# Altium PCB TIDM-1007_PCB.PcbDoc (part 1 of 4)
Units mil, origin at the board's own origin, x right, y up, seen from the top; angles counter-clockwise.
Board outline 9645.67 x 3346.46 mil, 6 copper layers (Top Layer, Signal Layer 1, Signal Layer 2, Signal Layer 3, Signal Layer 4, Bottom Layer), stack 60.2 mil thick; 189 components, 109 nets, 620 pads, 278 vias.
Unrouted connection lines stored in the file: 5.
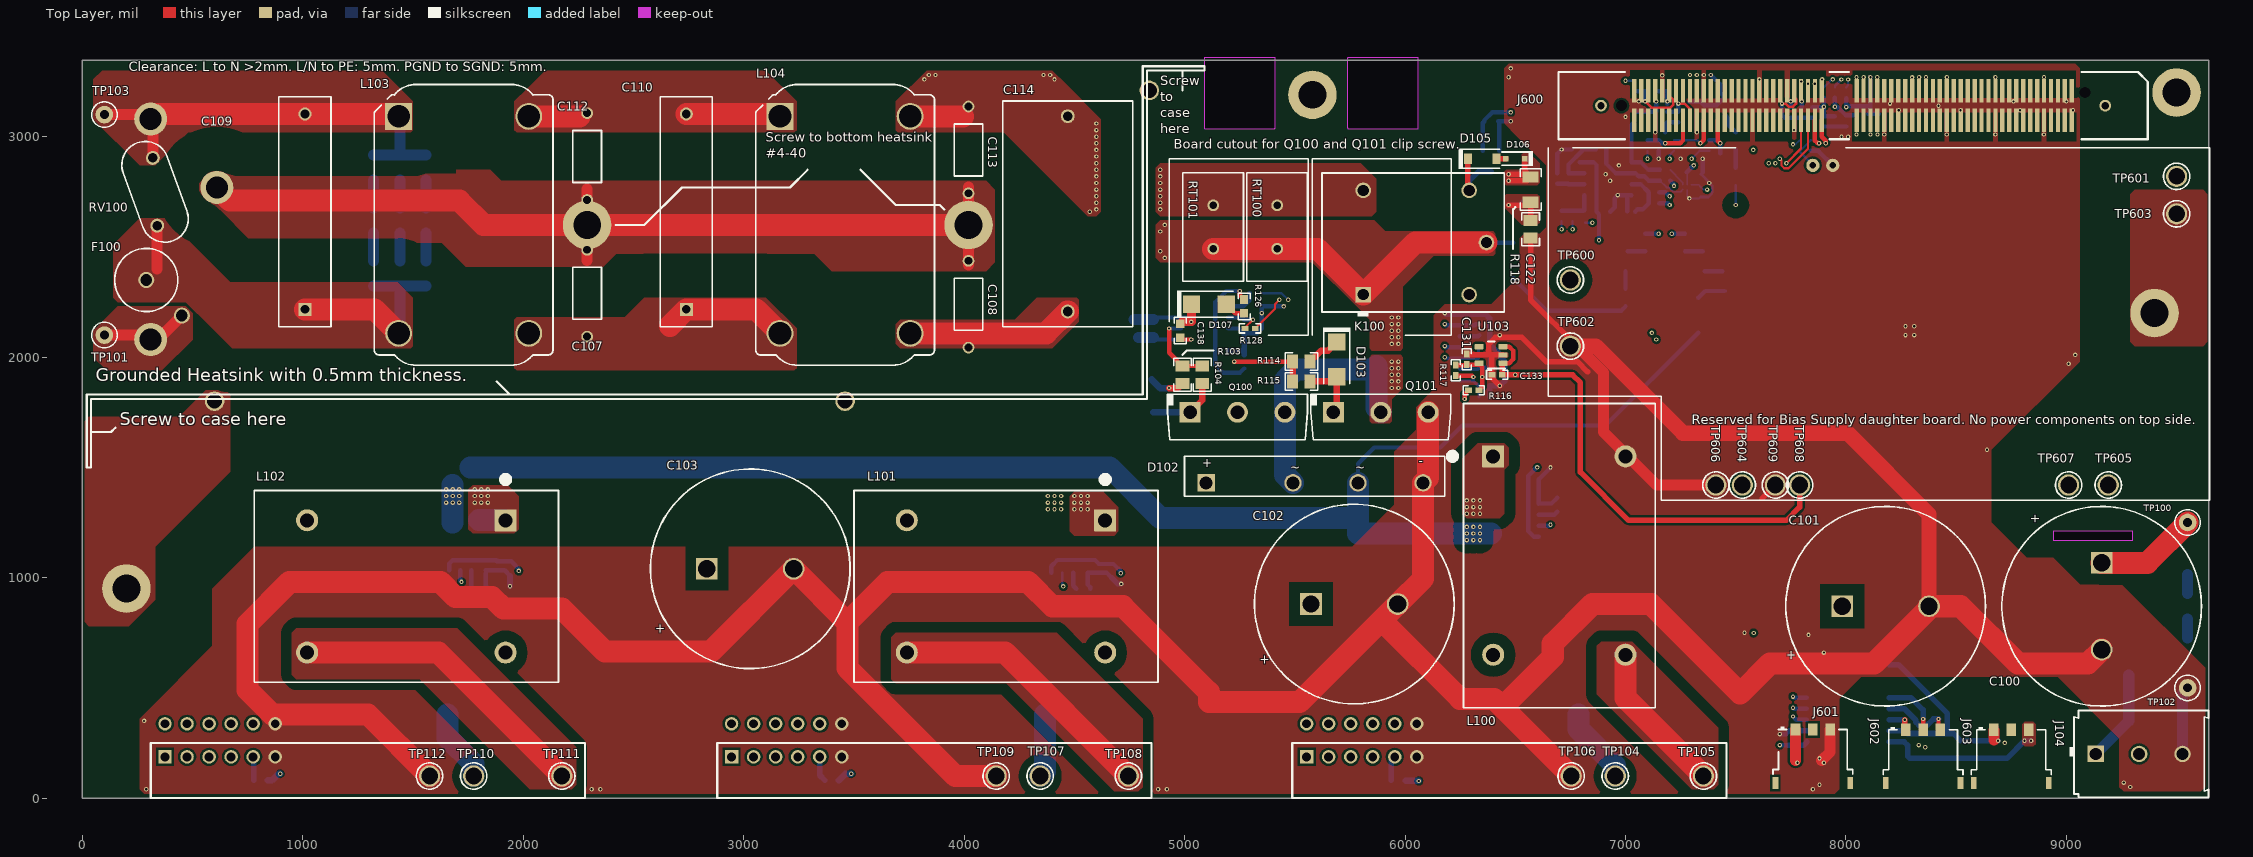
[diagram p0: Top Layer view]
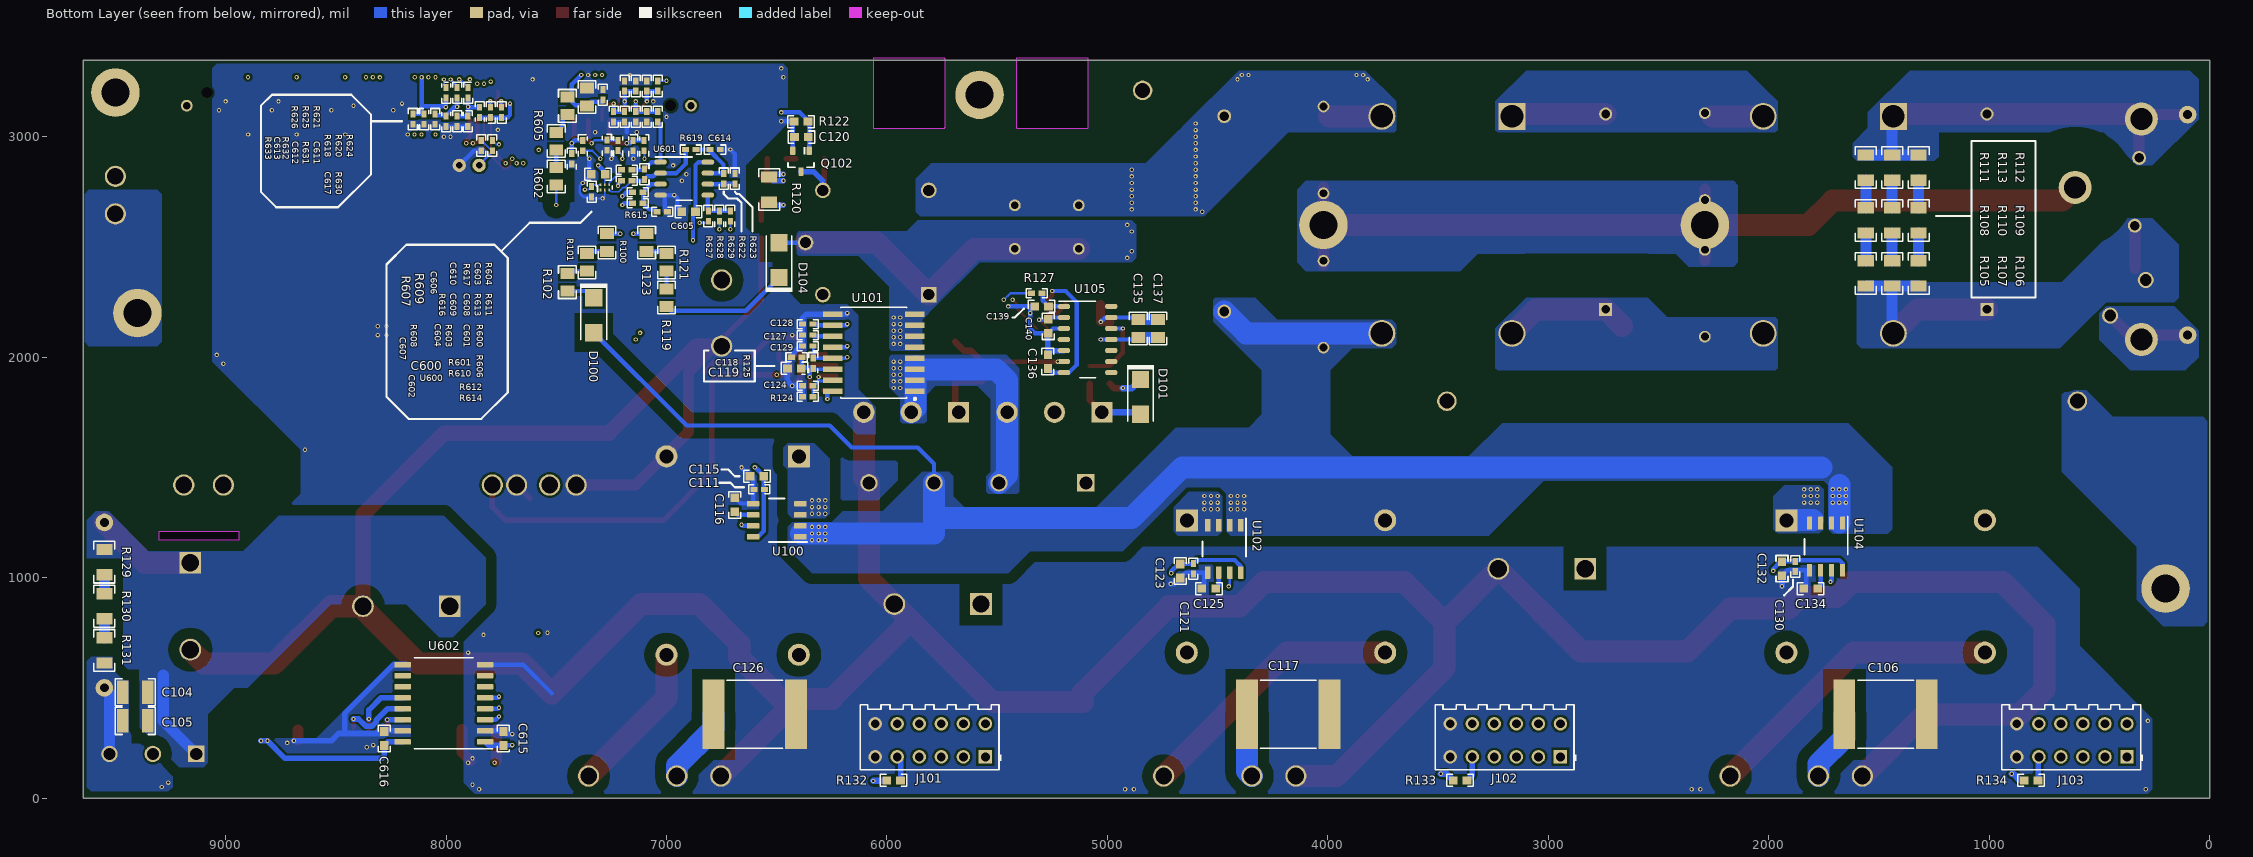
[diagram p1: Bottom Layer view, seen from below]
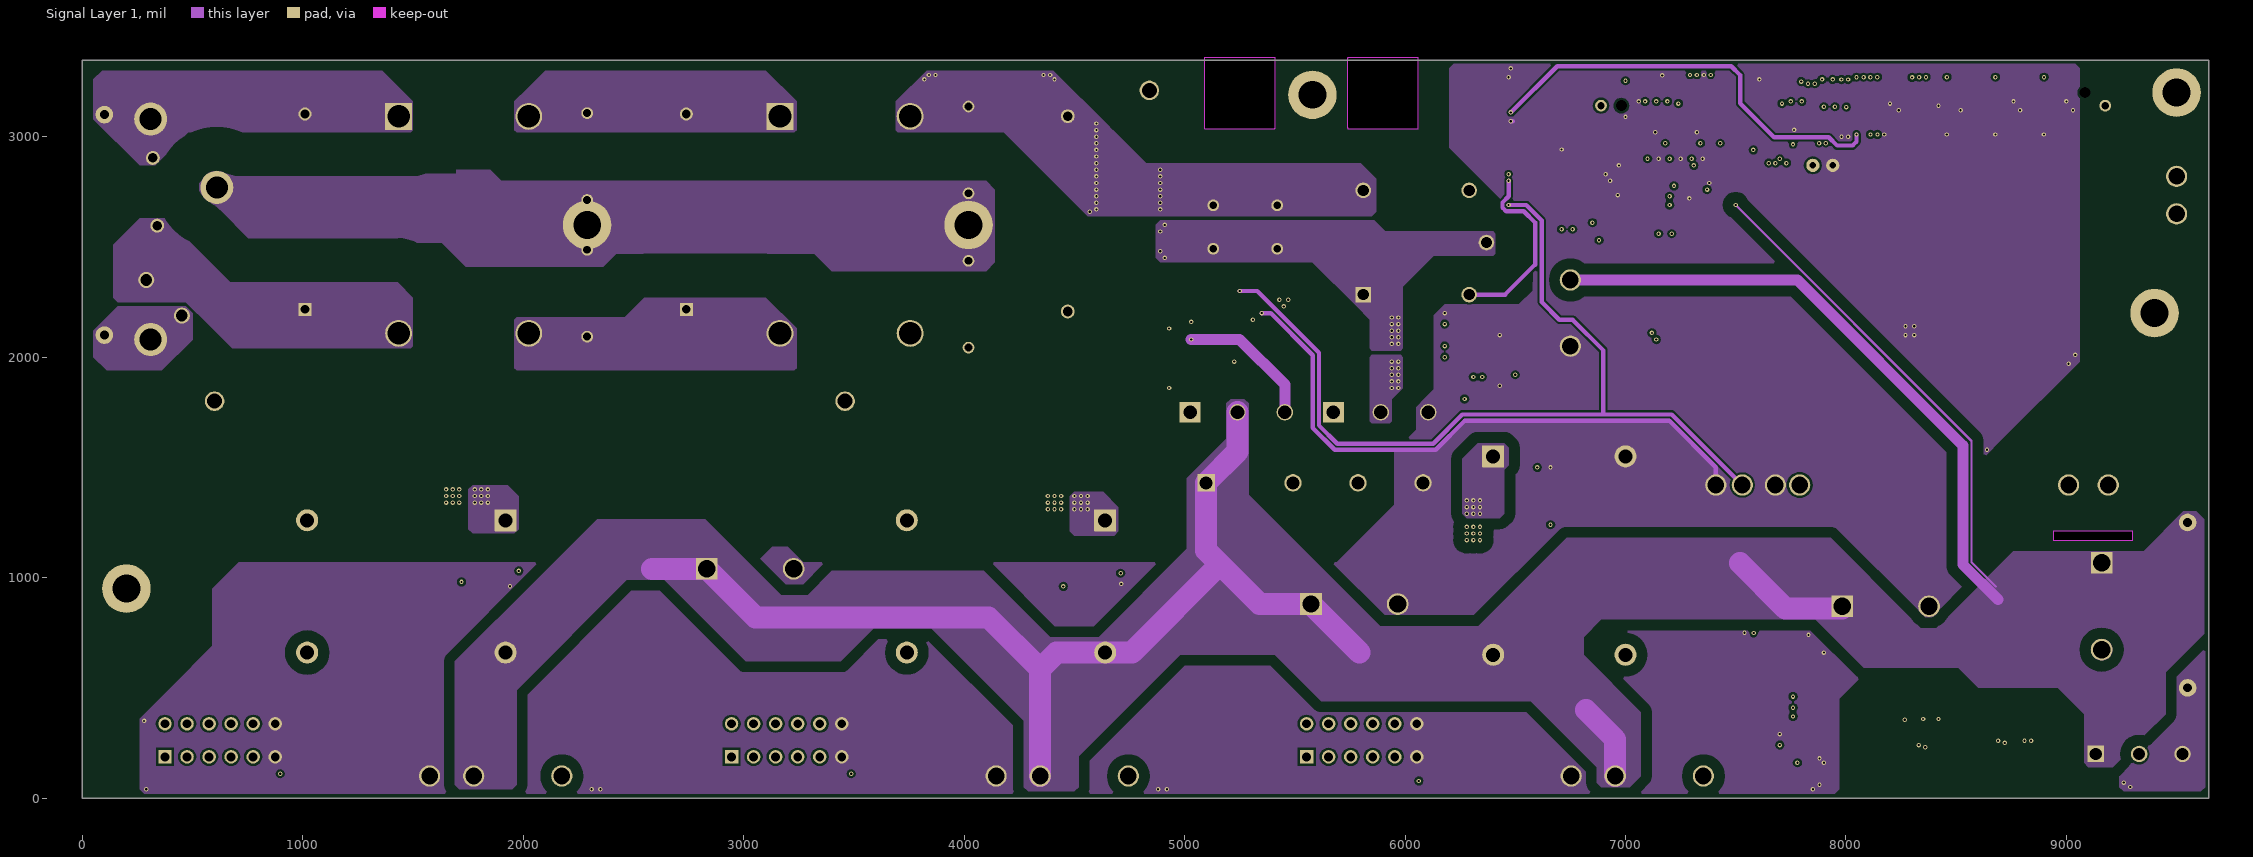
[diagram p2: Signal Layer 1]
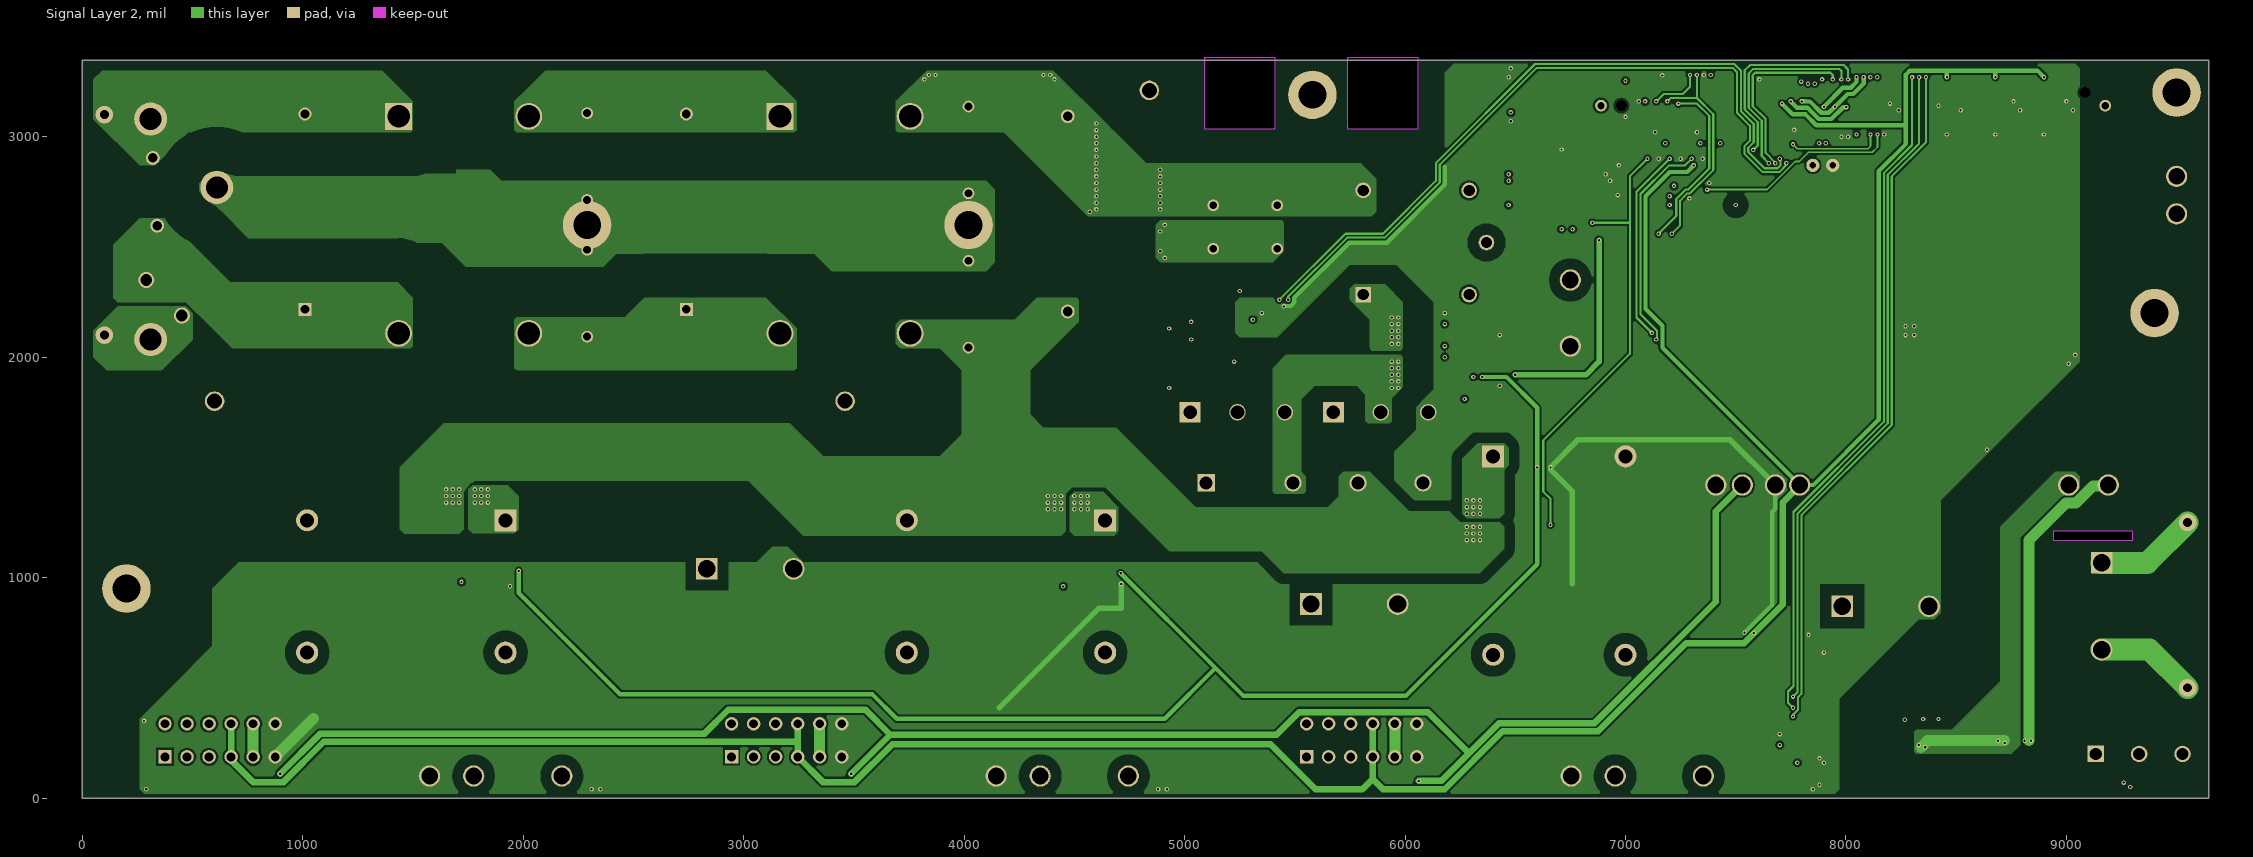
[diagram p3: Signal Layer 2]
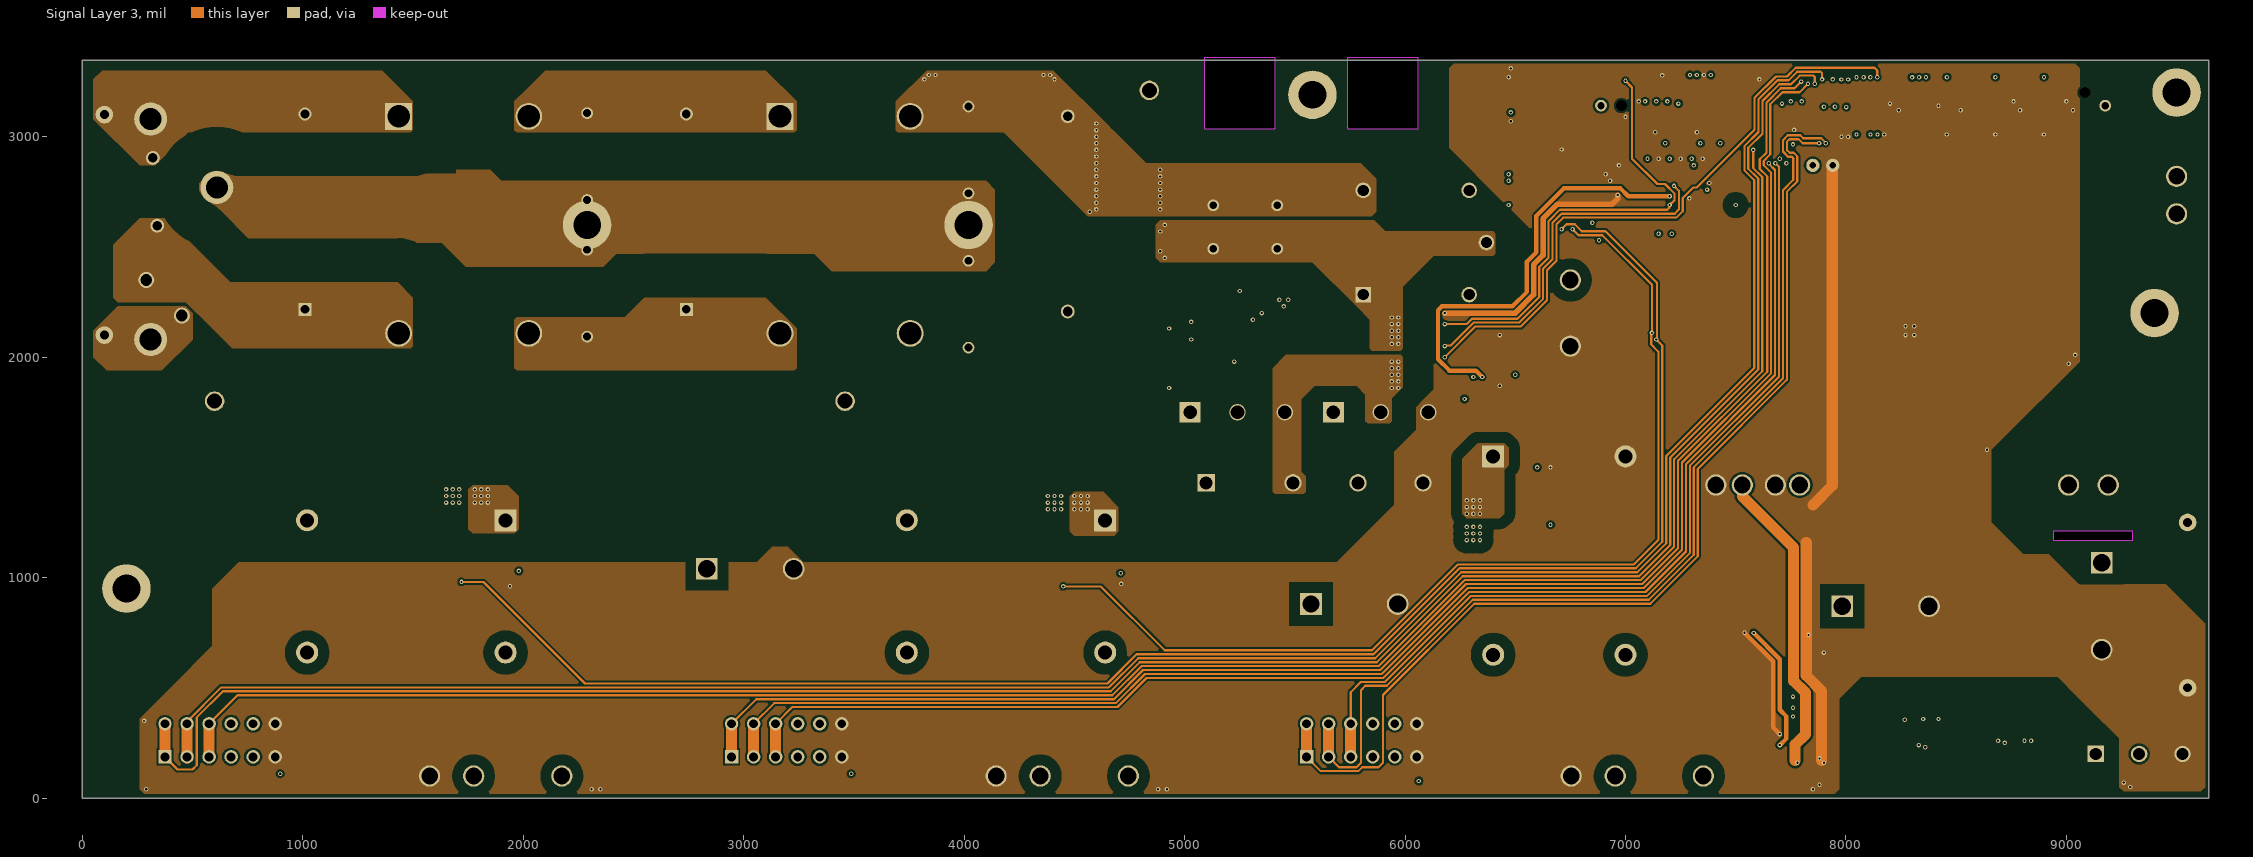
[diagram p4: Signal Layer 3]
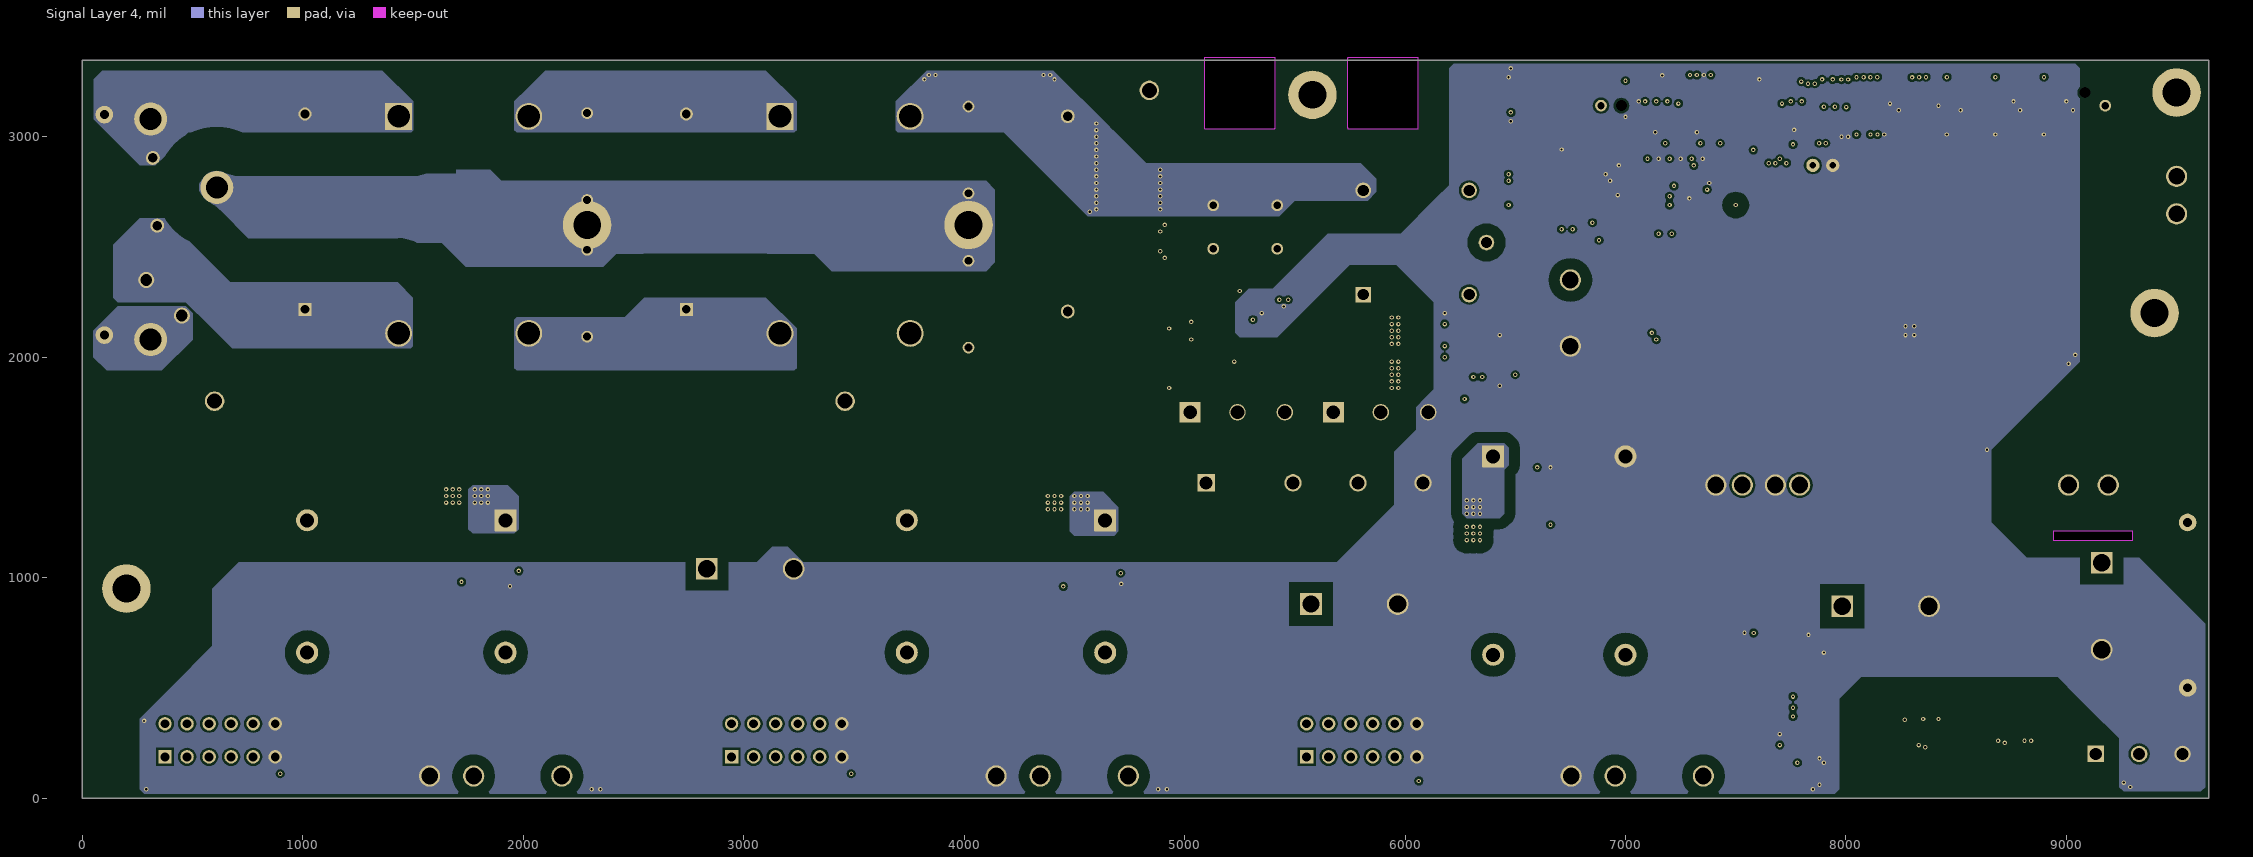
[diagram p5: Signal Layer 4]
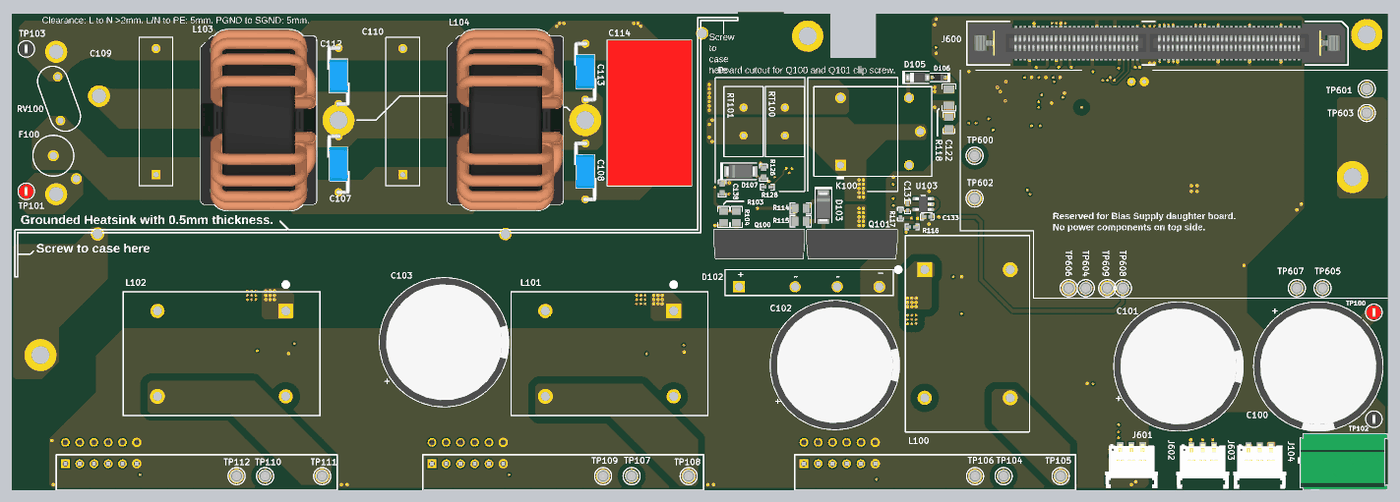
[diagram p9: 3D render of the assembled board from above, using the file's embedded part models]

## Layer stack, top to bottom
Top Solder: solder mask 0.4, Solder Resist, Dk 3.5
Top Layer: signal copper 2.8
Dielectric1: prepreg 7, Dk 4.2
Signal Layer 1: signal copper 1.4
Dielectric 3: core 14, FR-4, Dk 4.2
Signal Layer 2: signal copper 1.4
Dielectric 4: prepreg 7, Dk 4.2
Signal Layer 3: signal copper 1.4
Dielectric 5: core 14, FR-4, Dk 4.2
Signal Layer 4: signal copper 1.4
Dielectric 2: prepreg 7, Dk 4.2
Bottom Layer: signal copper 2.8
Bottom Solder: solder mask 0.4, Solder Resist, Dk 3.5

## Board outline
0,0 9645.67,0 9645.67,3346.46 0,3346.46
cut-out: 8940,1170 9300,1170 9300,1210 8940,1210
cut-out: 5089,3040 ccw(c5092.52,3040) 5092.52,3036.48 5407.48,3036.48 ccw(c5407.48,3040) 5411,3040 5411,3354.96 ccw(c5407.48,3354.96) 5407.48,3358.48 5092.52,3358.48 ccw(c5092.52,3354.96) 5089,3354.96
cut-out: 5739,3040 ccw(c5742.52,3040) 5742.52,3036.48 6057.48,3036.48 ccw(c6057.48,3040) 6061,3040 6061,3354.96 ccw(c6057.48,3354.96) 6057.48,3358.48 5742.52,3358.48 ccw(c5742.52,3354.96) 5739,3354.96

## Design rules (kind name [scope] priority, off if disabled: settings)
AcuteAngle [All] p1: minimum=4.50000000000000E+0001 checktracksonly=FALSE
AssemblyTestPointUsage [All] p1: valid=2
Clearance Clearance_3 [InNet('EARTH') vs Not InNet('EARTH') And Not InNet('12VS')] p1: gap=200 ignorepadtopadclearanceinfootprint=FALSE except(0: Arc-Hole Track-Hole SMDPad-Hole THPad-Hole Via-Hole Fill-Hole Poly-Hole Region-Hole Text-Hole)
Clearance Clearance_1 [InNetClass('HV') vs InNetClass('MV')] p2: gap=25 ignorepadtopadclearanceinfootprint=FALSE except(0: Arc-Hole Track-Hole SMDPad-Hole THPad-Hole Via-Hole Fill-Hole Poly-Hole Region-Hole Text-Hole)
Clearance Clearance_2 [InNetClass('HV') vs Not InNetClass('HV')] p3: gap=50 ignorepadtopadclearanceinfootprint=FALSE except(0: Arc-Hole Track-Hole SMDPad-Hole THPad-Hole Via-Hole Fill-Hole Poly-Hole Region-Hole Text-Hole)
Clearance Clearance_Keepouts [((IsTrack Or IsArc) And Not InPoly) And IsFree and IsKeepOut vs ((IsTrack Or IsArc) And Not InPoly) And IsFree and IsKeepOut] p4: gap=0 ignorepadtopadclearanceinfootprint=FALSE
Clearance Clearance_BoardEdge_MountingHoles [OnCopper and InComponentClass('Mounting Holes') vs IsKeepOut] p5: gap=40 ignorepadtopadclearanceinfootprint=FALSE except(0: Arc-Hole Track-Hole SMDPad-Hole THPad-Hole Via-Hole Fill-Hole Poly-Hole Region-Hole Text-Hole)
Clearance Clearance_BoardEdge_Poly [OnCopper and InPoly vs IsKeepOut] p6: gap=25 ignorepadtopadclearanceinfootprint=FALSE except(0: Arc-Hole Track-Hole SMDPad-Hole THPad-Hole Via-Hole Fill-Hole Poly-Hole Region-Hole Text-Hole)
Clearance Clearance_BoardEdge [OnCopper and Not InComponentClass('Logo') and not InComponentClass('FiducialMark') and not InRegion(1000,500,4000,800) and Not IsKeepout vs IsKeepOut] p7: gap=75 ignorepadtopadclearanceinfootprint=FALSE except(0: Arc-Hole Track-Hole SMDPad-Hole THPad-Hole Via-Hole Fill-Hole Poly-Hole Region-Hole Text-Hole)
Clearance Clearance_Poly [InPolygon] p8: gap=10 ignorepadtopadclearanceinfootprint=FALSE except(0: Arc-Hole Track-Hole SMDPad-Hole THPad-Hole Via-Hole Fill-Hole Poly-Hole Region-Hole Text-Hole)
Clearance [All] p9: gap=7.87 ignorepadtopadclearanceinfootprint=FALSE except(0: Arc-Hole Track-Hole SMDPad-Hole THPad-Hole Via-Hole Fill-Hole Poly-Hole Region-Hole Text-Hole)
ComponentClearance ComponentClearance_MountingHoles_FiducialMarks [InComponentClass('Mounting Holes') vs InComponentClass('FiducialMark')] p1: gap=20 collisioncheckmode=3 verticalgap=10 showdistances=FALSE
ComponentClearance ComponentClearance_Shunt [InComponentClass('Header') vs InComponentClass('Shunt')] p2: gap=0 collisioncheckmode=3 verticalgap=0 showdistances=FALSE
ComponentClearance ComponentClearance_Logo [InComponentClass('Logo')] p3: gap=5 collisioncheckmode=3 verticalgap=10 showdistances=FALSE
ComponentClearance ComponentClearance_ScrewToNut [(HasFootprint('NY PMS 440 0025 PH')) vs (HasFootprint('Keystone_1902C'))] p4: gap=20 collisioncheckmode=3 verticalgap=100000 showdistances=FALSE
ComponentClearance ComponentClearance_MountingHoles [InComponentClass('Mounting Holes')] p5: gap=20 collisioncheckmode=3 verticalgap=10 showdistances=FALSE
ComponentClearance ComponentClearance_SmallPassives [HasFootprint('0201*') or HasFootprint('0402*') or HasFootprint('0508') or HasFootprint('0603*') or HasFootprint('0612') or HasFootprint('0805*') or HasFootprint('0815*') or HasFootprint('0830*') or HasFootprint('1206*') or HasFootprint('1210*') or HasFootprint('1808*') or HasFootprint('1812*') or HasFootprint('1825*') or HasFootprint('2010*') or HasFootprint('2220*') or HasFootprint('2225*') or HasFootprint('2512*') or HasFootprint('2728*') or HasFootprint('3518*') vs HasFootprint('0201*') or HasFootprint('0402*') or HasFootprint('0508') or HasFootprint('0603*') or HasFootprint('0612') or HasFootprint('0805*') or HasFootprint('0815*') or HasFootprint('0830*') or HasFootprint('1206*') or HasFootprint('1210*') or HasFootprint('1808*') or HasFootprint('1812*') or HasFootprint('1825*') or HasFootprint('2010*') or HasFootprint('2220*') or HasFootprint('2225*') or HasFootprint('2512*') or HasFootprint('2728*') or HasFootprint('3518*')] p6: gap=20 collisioncheckmode=3 verticalgap=20 showdistances=FALSE
ComponentClearance ComponentClearance_THtoSMT [IsThruComponent vs IsSMTComponent] p7: gap=10 collisioncheckmode=3 verticalgap=10 showdistances=FALSE
ComponentClearance ComponentClearance_THtoTH [IsThruComponent vs IsThruComponent] p8: gap=10 collisioncheckmode=3 verticalgap=10 showdistances=FALSE
ComponentClearance [All] p9: gap=10 collisioncheckmode=3 verticalgap=10 showdistances=FALSE
DiffPairsRouting [All] p1: maxlimit=100 minlimit=10 mostfreqgap=10 toplayer_minwidth=15 toplayer_maxwidth=15 toplayer_prefwidth=15 midlayer1_minwidth=15 midlayer1_maxwidth=15 midlayer1_prefwidth=15 midlayer2_minwidth=15 midlayer2_maxwidth=15 midlayer2_prefwidth=15 midlayer3_minwidth=15 midlayer3_maxwidth=15 midlayer3_prefwidth=15 midlayer4_minwidth=15 midlayer4_maxwidth=15 midlayer4_prefwidth=15 bottomlayer_minwidth=15 bottomlayer_maxwidth=15 bottomlayer_prefwidth=15 maxuncoupledlength=1000
FabricationTestPointUsage TestPointUsage [All] p1: valid=2 allowmultiple=FALSE
FabricationTestpoint Testpoint [All] p1: side=3 testpointundercomponent=TRUE minsize=40 maxsize=100 preferedsize=60 minholesize=0 maxholesize=40 preferedholesize=32 testpointgrid=1 allowsidetop=TRUE allowsidebottom=TRUE usegrid=TRUE gridtolerance=0.01
FanoutControl Fanout_LCC [IsLCC] p1: bgadir=Out bgaviamode=Centered fanoutstyle=Auto fanoutdirection=Alternating viagrid=1 // Fanout_LCC (Default Rule)
FanoutControl Fanout_BGA [IsBGA] p2: bgadir=Out bgaviamode=Centered fanoutstyle=Auto fanoutdirection=Alternating viagrid=1 // Fanout_BGA (Default Rule)
FanoutControl Fanout_Default [All] p4: bgadir=Out bgaviamode=Centered fanoutstyle=Auto fanoutdirection=Alternating viagrid=1 // Fanout_Default (Default Rule)
FanoutControl Fanout_Small [(CompPinCount < 5)] p5: bgadir=Out bgaviamode=Centered fanoutstyle=Auto fanoutdirection=OutThenIn viagrid=1 // Fanout_Small (Default Rule)
Height [All] p1: minheight=0 maxheight=3000 prefheight=500
HoleSize [All] p1: absolutevalues=TRUE maxlimit=251 minlimit=7 maxpercent=80.000 minpercent=20.000
MinimumAnnularRing MinimumAnnularRing_ThermalPadVias [IsVia and InAnyComponent] p1: minimumring=5.91
MinimumAnnularRing [All] p2: minimumring=4.9
MinimumSolderMaskSliver MinimumSolderMaskSliver_Logo [InComponentClass('Logo') vs InComponentClass('Logo')] p1: minsoldermaskwidth=0.7
MinimumSolderMaskSliver [All] p2: minsoldermaskwidth=2
PlaneConnect [All] p1: planeconnectstyle=Direct reliefexpansion=10 reliefentries=4 reliefconductorwidth=10 reliefairgap=10
PolygonConnect PolygonConnect_26 [All vs IsNamedPolygon('12VP') Or  IsNamedPolygon('D106_1') Or  IsNamedPolygon('HVBUS') Or  IsNamedPolygon('Earth') Or  IsNamedPolygon('L101_1') Or  IsNamedPolygon('C110_2') Or  IsNamedPolygon('Earth') Or  IsNamedPolygon('SWNODE3') Or  IsNamedPolygon('C107_1') Or  IsNamedPolygon('L102_1') Or  IsNamedPolygon('L100_1') Or  IsNamedPolygon('AC_N') Or  IsNamedPolygon('C109_1') Or  IsNamedPolygon('Earth') Or  IsNamedPolygon('C109_1') Or  IsNamedPolygon('F100_2') Or  IsNamedPolygon('-BRDG_N') Or  IsNamedPolygon('C109_1') Or  IsNamedPolygon('-BRDG_N') Or  IsNamedPolygon('Earth') Or  IsNamedPolygon('C113_2') Or  IsNamedPolygon('Earth') Or  IsNamedPolygon('C110_2') Or  IsNamedPolygon('C107_1') Or  IsNamedPolygon('SWNODE2') Or  IsNamedPolygon('SGND2') Or  IsNamedPolygon('C113_2') Or  IsNamedPolygon('C109_2') Or  IsNamedPolygon('L101_1') Or  IsNamedPolygon('AC_N') Or  IsNamedPolygon('C113_2') Or  IsNamedPolygon('SWNODE2') Or  IsNamedPolygon('-BRDG_N') Or  IsNamedPolygon('C113_2') Or  IsNamedPolygon('AC_N') Or  IsNamedPolygon('5VS') Or  IsNamedPolygon('C110_2') Or  IsNamedPolygon('PGND') Or  IsNamedPolygon('HVBUS') Or  IsNamedPolygon('C107_1') Or  IsNamedPolygon('F100_2') Or  IsNamedPolygon('AC_L') Or  IsNamedPolygon('SGND2') Or  IsNamedPolygon('-BRDG_N') Or  IsNamedPolygon('C109_1') Or  IsNamedPolygon('L101_1') Or  IsNamedPolygon('C109_2') Or  IsNamedPolygon('C110_2') Or  IsNamedPolygon('C109_2') Or  IsNamedPolygon('-BRDG_N') Or  IsNamedPolygon('C110_2') Or  IsNamedPolygon('C109_1') Or  IsNamedPolygon('C109_2') Or  IsNamedPolygon('F100_2') Or  IsNamedPolygon('AC_N') Or  IsNamedPolygon('C109_2') Or  IsNamedPolygon('F100_2') Or  IsNamedPolygon('C107_1') Or  IsNamedPolygon('C113_2') Or  IsNamedPolygon('F100_2') Or  IsNamedPolygon('AC_N') Or  IsNamedPolygon('C110_2') Or  IsNamedPolygon('SWNODE1') Or  IsNamedPolygon('C109_2') Or  IsNamedPolygon('C109_1') Or  IsNamedPolygon('C107_1') Or  IsNamedPolygon('F100_2') Or  IsNamedPolygon('C107_1') Or  IsNamedPolygon('AC_N') Or  IsNamedPolygon('L100_1') Or  IsNamedPolygon('Earth') Or  IsNamedPolygon('C113_2') Or  IsNamedPolygon('SWNODE1') Or  IsNamedPolygon('AC_L') Or  IsNamedPolygon('L102_1') Or  IsNamedPolygon('SWNODE3') Or  IsNamedPolygon('AC_L')] p1: connectstyle=Direct reliefconductorwidth=10 reliefentries=4 polygonreliefangle="90 Angle" airgapwidth=10
PolygonConnect PolygonConnect_25 [All vs IsNamedPolygon('12VP') Or  IsNamedPolygon('SWNODE2') Or  IsNamedPolygon('F100_2') Or  IsNamedPolygon('AC_N') Or  IsNamedPolygon('C113_2') Or  IsNamedPolygon('-BRDG_N') Or  IsNamedPolygon('L102_1') Or  IsNamedPolygon('Earth') Or  IsNamedPolygon('SWNODE3') Or  IsNamedPolygon('L101_1') Or  IsNamedPolygon('C109_2') Or  IsNamedPolygon('C107_1') Or  IsNamedPolygon('C110_2') Or  IsNamedPolygon('C109_2') Or  IsNamedPolygon('C110_2') Or  IsNamedPolygon('5VS') Or  IsNamedPolygon('L101_1') Or  IsNamedPolygon('-BRDG_N') Or  IsNamedPolygon('AC_L') Or  IsNamedPolygon('AC_N') Or  IsNamedPolygon('F100_2') Or  IsNamedPolygon('AC_N') Or  IsNamedPolygon('-BRDG_N') Or  IsNamedPolygon('AC_L') Or  IsNamedPolygon('L102_1') Or  IsNamedPolygon('C109_2') Or  IsNamedPolygon('L100_1') Or  IsNamedPolygon('C113_2') Or  IsNamedPolygon('C113_2') Or  IsNamedPolygon('C113_2') Or  IsNamedPolygon('C109_2') Or  IsNamedPolygon('Earth') Or  IsNamedPolygon('AC_N') Or  IsNamedPolygon('C107_1') Or  IsNamedPolygon('C107_1') Or  IsNamedPolygon('F100_2') Or  IsNamedPolygon('C109_1') Or  IsNamedPolygon('-BRDG_N') Or  IsNamedPolygon('C110_2') Or  IsNamedPolygon('AC_L') Or  IsNamedPolygon('C113_2') Or  IsNamedPolygon('Earth') Or  IsNamedPolygon('C109_1') Or  IsNamedPolygon('C110_2') Or  IsNamedPolygon('SWNODE3') Or  IsNamedPolygon('C109_1') Or  IsNamedPolygon('C109_2') Or  IsNamedPolygon('C107_1') Or  IsNamedPolygon('F100_2') Or  IsNamedPolygon('D106_1') Or  IsNamedPolygon('C109_1') Or  IsNamedPolygon('L101_1') Or  IsNamedPolygon('C110_2') Or  IsNamedPolygon('C107_1') Or  IsNamedPolygon('C109_2') Or  IsNamedPolygon('C109_1') Or  IsNamedPolygon('Earth') Or  IsNamedPolygon('HVBUS') Or  IsNamedPolygon('Earth') Or  IsNamedPolygon('AC_N') Or  IsNamedPolygon('SWNODE2') Or  IsNamedPolygon('AC_N') Or  IsNamedPolygon('Earth') Or  IsNamedPolygon('F100_2') Or  IsNamedPolygon('C110_2') Or  IsNamedPolygon('F100_2') Or  IsNamedPolygon('SWNODE1') Or  IsNamedPolygon('C113_2') Or  IsNamedPolygon('C107_1') Or  IsNamedPolygon('C109_1') Or  IsNamedPolygon('L100_1') Or  IsNamedPolygon('-BRDG_N') Or  IsNamedPolygon('SWNODE1')] p2: connectstyle=Direct reliefconductorwidth=10 reliefentries=4 polygonreliefangle="90 Angle" airgapwidth=10
PolygonConnect PolygonConnect_24 [All vs IsNamedPolygon('12VP') Or  IsNamedPolygon('C113_2') Or  IsNamedPolygon('C107_1') Or  IsNamedPolygon('L100_1') Or  IsNamedPolygon('C107_1') Or  IsNamedPolygon('C107_1') Or  IsNamedPolygon('5VS') Or  IsNamedPolygon('C113_2') Or  IsNamedPolygon('SWNODE3') Or  IsNamedPolygon('AC_N') Or  IsNamedPolygon('C113_2') Or  IsNamedPolygon('C113_2') Or  IsNamedPolygon('C109_2') Or  IsNamedPolygon('F100_2') Or  IsNamedPolygon('F100_2') Or  IsNamedPolygon('C113_2') Or  IsNamedPolygon('Earth') Or  IsNamedPolygon('C109_2') Or  IsNamedPolygon('C109_1') Or  IsNamedPolygon('C110_2') Or  IsNamedPolygon('-BRDG_N') Or  IsNamedPolygon('AC_N') Or  IsNamedPolygon('C110_2') Or  IsNamedPolygon('L102_1') Or  IsNamedPolygon('AC_N') Or  IsNamedPolygon('D106_1') Or  IsNamedPolygon('L102_1') Or  IsNamedPolygon('Earth') Or  IsNamedPolygon('F100_2') Or  IsNamedPolygon('-BRDG_N') Or  IsNamedPolygon('C109_1') Or  IsNamedPolygon('SWNODE2') Or  IsNamedPolygon('C109_2') Or  IsNamedPolygon('SWNODE1') Or  IsNamedPolygon('-BRDG_N') Or  IsNamedPolygon('-BRDG_N') Or  IsNamedPolygon('-BRDG_N') Or  IsNamedPolygon('AC_N') Or  IsNamedPolygon('AC_L') Or  IsNamedPolygon('AC_L') Or  IsNamedPolygon('SWNODE3') Or  IsNamedPolygon('C113_2') Or  IsNamedPolygon('C109_1') Or  IsNamedPolygon('C109_2') Or  IsNamedPolygon('Earth') Or  IsNamedPolygon('SWNODE1') Or  IsNamedPolygon('C110_2') Or  IsNamedPolygon('SWNODE2') Or  IsNamedPolygon('F100_2') Or  IsNamedPolygon('C107_1') Or  IsNamedPolygon('F100_2') Or  IsNamedPolygon('L100_1') Or  IsNamedPolygon('C107_1') Or  IsNamedPolygon('C110_2') Or  IsNamedPolygon('L101_1') Or  IsNamedPolygon('C110_2') Or  IsNamedPolygon('AC_N') Or  IsNamedPolygon('C110_2') Or  IsNamedPolygon('Earth') Or  IsNamedPolygon('AC_N') Or  IsNamedPolygon('C109_2') Or  IsNamedPolygon('Earth') Or  IsNamedPolygon('C109_2') Or  IsNamedPolygon('C109_1') Or  IsNamedPolygon('C109_1') Or  IsNamedPolygon('C109_1') Or  IsNamedPolygon('C107_1') Or  IsNamedPolygon('L101_1') Or  IsNamedPolygon('L101_1') Or  IsNamedPolygon('F100_2') Or  IsNamedPolygon('Earth')] p3: connectstyle=Direct reliefconductorwidth=10 reliefentries=4 polygonreliefangle="90 Angle" airgapwidth=10
PolygonConnect PolygonConnect_23 [All vs IsNamedPolygon('C110_2') Or  IsNamedPolygon('C110_2') Or  IsNamedPolygon('C109_2') Or  IsNamedPolygon('C110_2') Or  IsNamedPolygon('C110_2') Or  IsNamedPolygon('C110_2') Or  IsNamedPolygon('C109_2') Or  IsNamedPolygon('12VP') Or  IsNamedPolygon('5VS') Or  IsNamedPolygon('D106_1') Or  IsNamedPolygon('C109_2') Or  IsNamedPolygon('C109_2') Or  IsNamedPolygon('C109_2') Or  IsNamedPolygon('C109_2') Or  IsNamedPolygon('C109_1') Or  IsNamedPolygon('F100_2') Or  IsNamedPolygon('C109_1') Or  IsNamedPolygon('Earth') Or  IsNamedPolygon('AC_N') Or  IsNamedPolygon('Earth') Or  IsNamedPolygon('F100_2') Or  IsNamedPolygon('C109_1') Or  IsNamedPolygon('Earth') Or  IsNamedPolygon('C109_1') Or  IsNamedPolygon('-BRDG_N') Or  IsNamedPolygon('C107_1') Or  IsNamedPolygon('AC_L') Or  IsNamedPolygon('C109_1') Or  IsNamedPolygon('SWNODE2') Or  IsNamedPolygon('C113_2') Or  IsNamedPolygon('SWNODE1') Or  IsNamedPolygon('-BRDG_N') Or  IsNamedPolygon('-BRDG_N') Or  IsNamedPolygon('Earth') Or  IsNamedPolygon('C107_1') Or  IsNamedPolygon('SWNODE1') Or  IsNamedPolygon('F100_2') Or  IsNamedPolygon('-BRDG_N') Or  IsNamedPolygon('C107_1') Or  IsNamedPolygon('AC_N') Or  IsNamedPolygon('AC_N') Or  IsNamedPolygon('Earth') Or  IsNamedPolygon('-BRDG_N') Or  IsNamedPolygon('C107_1') Or  IsNamedPolygon('SWNODE3') Or  IsNamedPolygon('C107_1') Or  IsNamedPolygon('C113_2') Or  IsNamedPolygon('F100_2') Or  IsNamedPolygon('SWNODE3') Or  IsNamedPolygon('Earth') Or  IsNamedPolygon('C109_1') Or  IsNamedPolygon('C113_2') Or  IsNamedPolygon('F100_2') Or  IsNamedPolygon('C113_2') Or  IsNamedPolygon('C110_2') Or  IsNamedPolygon('AC_L') Or  IsNamedPolygon('AC_N') Or  IsNamedPolygon('AC_N') Or  IsNamedPolygon('AC_N') Or  IsNamedPolygon('SWNODE2') Or  IsNamedPolygon('F100_2') Or  IsNamedPolygon('C113_2') Or  IsNamedPolygon('AC_N') Or  IsNamedPolygon('-BRDG_N') Or  IsNamedPolygon('C107_1') Or  IsNamedPolygon('C113_2')] p4: connectstyle=Direct reliefconductorwidth=10 reliefentries=4 polygonreliefangle="90 Angle" airgapwidth=10
PolygonConnect PolygonConnect_22 [All vs IsNamedPolygon('12VP') Or  IsNamedPolygon('C107_1') Or  IsNamedPolygon('C107_1') Or  IsNamedPolygon('C109_1') Or  IsNamedPolygon('Earth') Or  IsNamedPolygon('Earth') Or  IsNamedPolygon('Earth') Or  IsNamedPolygon('C109_1') Or  IsNamedPolygon('C107_1') Or  IsNamedPolygon('C109_1') Or  IsNamedPolygon('Earth') Or  IsNamedPolygon('Earth') Or  IsNamedPolygon('C109_1') Or  IsNamedPolygon('AC_L') Or  IsNamedPolygon('C107_1') Or  IsNamedPolygon('C107_1') Or  IsNamedPolygon('AC_L') Or  IsNamedPolygon('C107_1') Or  IsNamedPolygon('Earth') Or  IsNamedPolygon('AC_N') Or  IsNamedPolygon('C113_2') Or  IsNamedPolygon('C110_2') Or  IsNamedPolygon('C109_1') Or  IsNamedPolygon('F100_2') Or  IsNamedPolygon('C110_2') Or  IsNamedPolygon('C113_2') Or  IsNamedPolygon('AC_N') Or  IsNamedPolygon('-BRDG_N') Or  IsNamedPolygon('AC_N') Or  IsNamedPolygon('F100_2') Or  IsNamedPolygon('C110_2') Or  IsNamedPolygon('F100_2') Or  IsNamedPolygon('-BRDG_N') Or  IsNamedPolygon('C113_2') Or  IsNamedPolygon('C110_2') Or  IsNamedPolygon('-BRDG_N') Or  IsNamedPolygon('AC_N') Or  IsNamedPolygon('C113_2') Or  IsNamedPolygon('F100_2') Or  IsNamedPolygon('F100_2') Or  IsNamedPolygon('F100_2') Or  IsNamedPolygon('AC_N') Or  IsNamedPolygon('C110_2') Or  IsNamedPolygon('AC_N') Or  IsNamedPolygon('-BRDG_N') Or  IsNamedPolygon('AC_N') Or  IsNamedPolygon('-BRDG_N') Or  IsNamedPolygon('-BRDG_N') Or  IsNamedPolygon('C109_1') Or  IsNamedPolygon('C113_2') Or  IsNamedPolygon('C113_2') Or  IsNamedPolygon('C109_2') Or  IsNamedPolygon('C109_2') Or  IsNamedPolygon('C109_2') Or  IsNamedPolygon('5VS') Or  IsNamedPolygon('C110_2') Or  IsNamedPolygon('D106_1') Or  IsNamedPolygon('C109_2') Or  IsNamedPolygon('C109_2') Or  IsNamedPolygon('C109_2')] p5: connectstyle=Direct reliefconductorwidth=10 reliefentries=4 polygonreliefangle="90 Angle" airgapwidth=10
PolygonConnect PolygonConnect_21 [All vs IsNamedPolygon('C110_2') Or  IsNamedPolygon('C113_2') Or  IsNamedPolygon('C113_2') Or  IsNamedPolygon('C113_2') Or  IsNamedPolygon('C110_2') Or  IsNamedPolygon('C109_2') Or  IsNamedPolygon('C109_2') Or  IsNamedPolygon('C110_2') Or  IsNamedPolygon('D106_1') Or  IsNamedPolygon('C110_2') Or  IsNamedPolygon('C109_2') Or  IsNamedPolygon('C113_2') Or  IsNamedPolygon('C109_2') Or  IsNamedPolygon('5VS') Or  IsNamedPolygon('C109_2') Or  IsNamedPolygon('C110_2') Or  IsNamedPolygon('C109_2') Or  IsNamedPolygon('C110_2') Or  IsNamedPolygon('12VP') Or  IsNamedPolygon('C113_2') Or  IsNamedPolygon('C107_1') Or  IsNamedPolygon('AC_N') Or  IsNamedPolygon('C107_1') Or  IsNamedPolygon('C109_1') Or  IsNamedPolygon('Earth') Or  IsNamedPolygon('F100_2') Or  IsNamedPolygon('AC_N') Or  IsNamedPolygon('C113_2') Or  IsNamedPolygon('Earth') Or  IsNamedPolygon('F100_2') Or  IsNamedPolygon('C107_1') Or  IsNamedPolygon('Earth') Or  IsNamedPolygon('F100_2') Or  IsNamedPolygon('-BRDG_N') Or  IsNamedPolygon('-BRDG_N') Or  IsNamedPolygon('-BRDG_N') Or  IsNamedPolygon('-BRDG_N') Or  IsNamedPolygon('-BRDG_N') Or  IsNamedPolygon('AC_L') Or  IsNamedPolygon('C109_1') Or  IsNamedPolygon('AC_N') Or  IsNamedPolygon('C109_1') Or  IsNamedPolygon('F100_2') Or  IsNamedPolygon('-BRDG_N') Or  IsNamedPolygon('AC_N') Or  IsNamedPolygon('C109_1') Or  IsNamedPolygon('C107_1') Or  IsNamedPolygon('Earth') Or  IsNamedPolygon('C109_1') Or  IsNamedPolygon('AC_N') Or  IsNamedPolygon('F100_2') Or  IsNamedPolygon('Earth') Or  IsNamedPolygon('Earth') Or  IsNamedPolygon('C107_1') Or  IsNamedPolygon('AC_N') Or  IsNamedPolygon('F100_2') Or  IsNamedPolygon('C109_1') Or  IsNamedPolygon('AC_N') Or  IsNamedPolygon('C107_1')] p6: connectstyle=Direct reliefconductorwidth=10 reliefentries=4 polygonreliefangle="90 Angle" airgapwidth=10
PolygonConnect PolygonConnect_20 [All vs IsNamedPolygon('12VP') Or  IsNamedPolygon('C110_2') Or  IsNamedPolygon('C110_2') Or  IsNamedPolygon('-BRDG_N') Or  IsNamedPolygon('C113_2') Or  IsNamedPolygon('-BRDG_N') Or  IsNamedPolygon('F100_2') Or  IsNamedPolygon('C113_2') Or  IsNamedPolygon('-BRDG_N') Or  IsNamedPolygon('AC_N') Or  IsNamedPolygon('C110_2') Or  IsNamedPolygon('C110_2') Or  IsNamedPolygon('C113_2') Or  IsNamedPolygon('AC_N') Or  IsNamedPolygon('AC_N') Or  IsNamedPolygon('C113_2') Or  IsNamedPolygon('AC_N') Or  IsNamedPolygon('F100_2') Or  IsNamedPolygon('C113_2') Or  IsNamedPolygon('-BRDG_N') Or  IsNamedPolygon('-BRDG_N') Or  IsNamedPolygon('F100_2') Or  IsNamedPolygon('F100_2') Or  IsNamedPolygon('AC_N') Or  IsNamedPolygon('C113_2') Or  IsNamedPolygon('F100_2') Or  IsNamedPolygon('F100_2') Or  IsNamedPolygon('AC_N') Or  IsNamedPolygon('AC_N') Or  IsNamedPolygon('-BRDG_N') Or  IsNamedPolygon('Earth') Or  IsNamedPolygon('C107_1') Or  IsNamedPolygon('Earth') Or  IsNamedPolygon('C107_1') Or  IsNamedPolygon('Earth') Or  IsNamedPolygon('C109_1') Or  IsNamedPolygon('C109_1') Or  IsNamedPolygon('C107_1') Or  IsNamedPolygon('C109_1') Or  IsNamedPolygon('C107_1') Or  IsNamedPolygon('C109_1') Or  IsNamedPolygon('C109_1') Or  IsNamedPolygon('Earth') Or  IsNamedPolygon('C107_1') Or  IsNamedPolygon('C107_1') Or  IsNamedPolygon('Earth') Or  IsNamedPolygon('C109_1') Or  IsNamedPolygon('C109_2') Or  IsNamedPolygon('C109_2') Or  IsNamedPolygon('C110_2') Or  IsNamedPolygon('C110_2') Or  IsNamedPolygon('C109_2') Or  IsNamedPolygon('C109_2') Or  IsNamedPolygon('5VS') Or  IsNamedPolygon('C109_2') Or  IsNamedPolygon('D106_1') Or  IsNamedPolygon('C109_2')] p7: connectstyle=Direct reliefconductorwidth=10 reliefentries=4 polygonreliefangle="90 Angle" airgapwidth=10
PolygonConnect PolygonConnect_19 [All vs IsNamedPolygon('C107_1') Or  IsNamedPolygon('C107_1') Or  IsNamedPolygon('C109_1') Or  IsNamedPolygon('C107_1') Or  IsNamedPolygon('C109_1') Or  IsNamedPolygon('C107_1') Or  IsNamedPolygon('F100_2') Or  IsNamedPolygon('C109_1') Or  IsNamedPolygon('C107_1') Or  IsNamedPolygon('C107_1') Or  IsNamedPolygon('C109_1') Or  IsNamedPolygon('C109_1') Or  IsNamedPolygon('C109_1') Or  IsNamedPolygon('12VP') Or  IsNamedPolygon('C109_2') Or  IsNamedPolygon('F100_2') Or  IsNamedPolygon('F100_2') Or  IsNamedPolygon('-BRDG_N') Or  IsNamedPolygon('AC_N') Or  IsNamedPolygon('AC_N') Or  IsNamedPolygon('F100_2') Or  IsNamedPolygon('AC_N') Or  IsNamedPolygon('C113_2') Or  IsNamedPolygon('C110_2') Or  IsNamedPolygon('AC_N') Or  IsNamedPolygon('C113_2') Or  IsNamedPolygon('C110_2') Or  IsNamedPolygon('5VS') Or  IsNamedPolygon('C109_2') Or  IsNamedPolygon('C113_2') Or  IsNamedPolygon('AC_N') Or  IsNamedPolygon('-BRDG_N') Or  IsNamedPolygon('F100_2') Or  IsNamedPolygon('C109_2') Or  IsNamedPolygon('-BRDG_N') Or  IsNamedPolygon('D106_1') Or  IsNamedPolygon('C110_2') Or  IsNamedPolygon('C113_2') Or  IsNamedPolygon('C109_2') Or  IsNamedPolygon('C110_2') Or  IsNamedPolygon('C109_2') Or  IsNamedPolygon('-BRDG_N') Or  IsNamedPolygon('C110_2') Or  IsNamedPolygon('AC_N') Or  IsNamedPolygon('C113_2') Or  IsNamedPolygon('F100_2') Or  IsNamedPolygon('C109_2') Or  IsNamedPolygon('C113_2') Or  IsNamedPolygon('-BRDG_N') Or  IsNamedPolygon('AC_N') Or  IsNamedPolygon('C110_2') Or  IsNamedPolygon('-BRDG_N')] p8: connectstyle=Direct reliefconductorwidth=10 reliefentries=4 polygonreliefangle="90 Angle" airgapwidth=10
PolygonConnect PolygonConnect_18 [All vs IsNamedPolygon('C109_2') Or  IsNamedPolygon('C109_2') Or  IsNamedPolygon('D106_1') Or  IsNamedPolygon('C109_2') Or  IsNamedPolygon('C110_2') Or  IsNamedPolygon('C110_2') Or  IsNamedPolygon('C109_2') Or  IsNamedPolygon('C109_2') Or  IsNamedPolygon('5VS') Or  IsNamedPolygon('C109_2') Or  IsNamedPolygon('F100_2') Or  IsNamedPolygon('AC_N') Or  IsNamedPolygon('AC_N') Or  IsNamedPolygon('-BRDG_N') Or  IsNamedPolygon('-BRDG_N') Or  IsNamedPolygon('C113_2') Or  IsNamedPolygon('-BRDG_N') Or  IsNamedPolygon('C110_2') Or  IsNamedPolygon('C113_2') Or  IsNamedPolygon('AC_N') Or  IsNamedPolygon('AC_N') Or  IsNamedPolygon('AC_N') Or  IsNamedPolygon('AC_N') Or  IsNamedPolygon('-BRDG_N') Or  IsNamedPolygon('C113_2') Or  IsNamedPolygon('C110_2') Or  IsNamedPolygon('F100_2') Or  IsNamedPolygon('C113_2') Or  IsNamedPolygon('AC_N') Or  IsNamedPolygon('F100_2') Or  IsNamedPolygon('C113_2') Or  IsNamedPolygon('C109_1') Or  IsNamedPolygon('F100_2') Or  IsNamedPolygon('C109_1') Or  IsNamedPolygon('-BRDG_N') Or  IsNamedPolygon('F100_2') Or  IsNamedPolygon('C113_2') Or  IsNamedPolygon('C110_2') Or  IsNamedPolygon('F100_2') Or  IsNamedPolygon('-BRDG_N') Or  IsNamedPolygon('C110_2') Or  IsNamedPolygon('C109_1') Or  IsNamedPolygon('C109_1') Or  IsNamedPolygon('C109_1') Or  IsNamedPolygon('C109_1') Or  IsNamedPolygon('12VP')] p9: connectstyle=Direct reliefconductorwidth=10 reliefentries=4 polygonreliefangle="90 Angle" airgapwidth=10
PolygonConnect PolygonConnect_17 [All vs IsNamedPolygon('AC_N') Or  IsNamedPolygon('-BRDG_N') Or  IsNamedPolygon('F100_2') Or  IsNamedPolygon('-BRDG_N') Or  IsNamedPolygon('-BRDG_N') Or  IsNamedPolygon('F100_2') Or  IsNamedPolygon('AC_N') Or  IsNamedPolygon('F100_2') Or  IsNamedPolygon('-BRDG_N') Or  IsNamedPolygon('F100_2') Or  IsNamedPolygon('AC_N') Or  IsNamedPolygon('F100_2') Or  IsNamedPolygon('-BRDG_N') Or  IsNamedPolygon('AC_N') Or  IsNamedPolygon('-BRDG_N') Or  IsNamedPolygon('F100_2') Or  IsNamedPolygon('C113_2') Or  IsNamedPolygon('D106_1') Or  IsNamedPolygon('C113_2') Or  IsNamedPolygon('AC_N') Or  IsNamedPolygon('C113_2') Or  IsNamedPolygon('C113_2') Or  IsNamedPolygon('C110_2') Or  IsNamedPolygon('C110_2') Or  IsNamedPolygon('C113_2') Or  IsNamedPolygon('5VS') Or  IsNamedPolygon('C109_2') Or  IsNamedPolygon('C109_2') Or  IsNamedPolygon('AC_N') Or  IsNamedPolygon('C110_2') Or  IsNamedPolygon('C113_2') Or  IsNamedPolygon('C109_2') Or  IsNamedPolygon('C110_2') Or  IsNamedPolygon('C109_2') Or  IsNamedPolygon('AC_N') Or  IsNamedPolygon('C109_2') Or  IsNamedPolygon('C110_2') Or  IsNamedPolygon('C109_2') Or  IsNamedPolygon('C110_2') Or  IsNamedPolygon('12VP')] p10: connectstyle=Direct reliefconductorwidth=10 reliefentries=4 polygonreliefangle="90 Angle" airgapwidth=10
PolygonConnect PolygonConnect_16 [All vs IsNamedPolygon('12VP') Or  IsNamedPolygon('AC_N') Or  IsNamedPolygon('C109_2') Or  IsNamedPolygon('AC_N') Or  IsNamedPolygon('AC_N') Or  IsNamedPolygon('AC_N') Or  IsNamedPolygon('C110_2') Or  IsNamedPolygon('C113_2') Or  IsNamedPolygon('C113_2') Or  IsNamedPolygon('C113_2') Or  IsNamedPolygon('C109_2') Or  IsNamedPolygon('C113_2') Or  IsNamedPolygon('5VS') Or  IsNamedPolygon('C110_2') Or  IsNamedPolygon('C110_2') Or  IsNamedPolygon('C109_2') Or  IsNamedPolygon('C109_2') Or  IsNamedPolygon('D106_1') Or  IsNamedPolygon('C110_2') Or  IsNamedPolygon('C110_2') Or  IsNamedPolygon('C113_2') Or  IsNamedPolygon('AC_N') Or  IsNamedPolygon('C109_2') Or  IsNamedPolygon('AC_N') Or  IsNamedPolygon('-BRDG_N') Or  IsNamedPolygon('C110_2') Or  IsNamedPolygon('-BRDG_N') Or  IsNamedPolygon('C109_2') Or  IsNamedPolygon('C113_2')] p11: connectstyle=Direct reliefconductorwidth=10 reliefentries=4 polygonreliefangle="90 Angle" airgapwidth=10
PolygonConnect PolygonConnect_15 [All vs IsNamedPolygon('12VP') Or  IsNamedPolygon('AC_N') Or  IsNamedPolygon('C113_2') Or  IsNamedPolygon('AC_N') Or  IsNamedPolygon('C110_2') Or  IsNamedPolygon('D106_1') Or  IsNamedPolygon('C110_2') Or  IsNamedPolygon('C113_2') Or  IsNamedPolygon('C109_2') Or  IsNamedPolygon('C113_2') Or  IsNamedPolygon('C109_2') Or  IsNamedPolygon('C113_2') Or  IsNamedPolygon('AC_N') Or  IsNamedPolygon('AC_N') Or  IsNamedPolygon('AC_N') Or  IsNamedPolygon('C109_2') Or  IsNamedPolygon('5VS') Or  IsNamedPolygon('C110_2') Or  IsNamedPolygon('C109_2') Or  IsNamedPolygon('C110_2') Or  IsNamedPolygon('C110_2') Or  IsNamedPolygon('C113_2') Or  IsNamedPolygon('C110_2') Or  IsNamedPolygon('C109_2') Or  IsNamedPolygon('C113_2') Or  IsNamedPolygon('C109_2') Or  IsNamedPolygon('AC_N')] p12: connectstyle=Direct reliefconductorwidth=10 reliefentries=4 polygonreliefangle="90 Angle" airgapwidth=10
PolygonConnect PolygonConnect_14 [All vs IsNamedPolygon('C110_2') Or  IsNamedPolygon('C110_2') Or  IsNamedPolygon('C109_2') Or  IsNamedPolygon('C113_2') Or  IsNamedPolygon('C113_2') Or  IsNamedPolygon('D106_1') Or  IsNamedPolygon('C110_2') Or  IsNamedPolygon('C113_2') Or  IsNamedPolygon('C110_2') Or  IsNamedPolygon('C109_2') Or  IsNamedPolygon('C109_2') Or  IsNamedPolygon('C109_2') Or  IsNamedPolygon('C113_2') Or  IsNamedPolygon('C113_2') Or  IsNamedPolygon('C110_2') Or  IsNamedPolygon('C110_2') Or  IsNamedPolygon('C113_2') Or  IsNamedPolygon('C109_2') Or  IsNamedPolygon('5VS') Or  IsNamedPolygon('C109_2') Or  IsNamedPolygon('12VP')] p13: connectstyle=Direct reliefconductorwidth=10 reliefentries=4 polygonreliefangle="90 Angle" airgapwidth=10
PolygonConnect PolygonConnect_13 [All vs IsNamedPolygon('C110_2') Or  IsNamedPolygon('C109_2') Or  IsNamedPolygon('D106_1') Or  IsNamedPolygon('C109_2') Or  IsNamedPolygon('C110_2') Or  IsNamedPolygon('C110_2') Or  IsNamedPolygon('C110_2') Or  IsNamedPolygon('C109_2') Or  IsNamedPolygon('C109_2') Or  IsNamedPolygon('C109_2') Or  IsNamedPolygon('C110_2') Or  IsNamedPolygon('C110_2') Or  IsNamedPolygon('C110_2') Or  IsNamedPolygon('5VS') Or  IsNamedPolygon('C109_2') Or  IsNamedPolygon('12VP')] p14: connectstyle=Direct reliefconductorwidth=10 reliefentries=4 polygonreliefangle="90 Angle" airgapwidth=10
PolygonConnect PolygonConnect_12 [All vs IsNamedPolygon('5VS') Or  IsNamedPolygon('C109_2') Or  IsNamedPolygon('D106_1') Or  IsNamedPolygon('C109_2') Or  IsNamedPolygon('C109_2') Or  IsNamedPolygon('C109_2') Or  IsNamedPolygon('C109_2') Or  IsNamedPolygon('C109_2') Or  IsNamedPolygon('12VP')] p15: connectstyle=Direct reliefconductorwidth=10 reliefentries=4 polygonreliefangle="90 Angle" airgapwidth=10
PolygonConnect PolygonConnect_11 [All vs IsNamedPolygon('D106_1') Or  IsNamedPolygon('12VP') Or  IsNamedPolygon('5VS')] p16: connectstyle=Direct reliefconductorwidth=10 reliefentries=4 polygonreliefangle="90 Angle" airgapwidth=10
PolygonConnect PolygonConnect_10 [All vs IsNamedPolygon('12VP') Or  IsNamedPolygon('D106_1')] p17: connectstyle=Direct reliefconductorwidth=10 reliefentries=4 polygonreliefangle="90 Angle" airgapwidth=10
PolygonConnect PolygonConnect_9 [All vs IsNamedPolygon('C11_1') Or  IsNamedPolygon('Vin') Or  IsNamedPolygon('Vin') Or  IsNamedPolygon('5V') Or  IsNamedPolygon('D6_2') Or  IsNamedPolygon('Q3_3') Or  IsNamedPolygon('GND2') Or  IsNamedPolygon('GND2') Or  IsNamedPolygon('GND') Or  IsNamedPolygon('Q3_4') Or  IsNamedPolygon('12V5') Or  IsNamedPolygon('GND') Or  IsNamedPolygon('12V5') Or  IsNamedPolygon('D3_1')] p18: connectstyle=Direct reliefconductorwidth=10 reliefentries=4 polygonreliefangle="90 Angle" airgapwidth=10
PolygonConnect PolygonConnect_8 [All vs IsNamedPolygon('C11_1') Or  IsNamedPolygon('Vin') Or  IsNamedPolygon('12V5') Or  IsNamedPolygon('Q3_3') Or  IsNamedPolygon('GND2') Or  IsNamedPolygon('GND2') Or  IsNamedPolygon('5V') Or  IsNamedPolygon('Q3_4') Or  IsNamedPolygon('12V5')] p19: connectstyle=Direct reliefconductorwidth=10 reliefentries=4 polygonreliefangle="90 Angle" airgapwidth=10
PolygonConnect PolygonConnect_7 [All vs IsNamedPolygon('GND2') Or  IsNamedPolygon('GND2') Or  IsNamedPolygon('5V') Or  IsNamedPolygon('12V5') Or  IsNamedPolygon('12V5') Or  IsNamedPolygon('C11_1')] p20: connectstyle=Direct reliefconductorwidth=10 reliefentries=4 polygonreliefangle="90 Angle" airgapwidth=10
PolygonConnect PolygonConnect_6 [All vs IsNamedPolygon('GND2') Or  IsNamedPolygon('SGND') Or  IsNamedPolygon('GND1') Or  IsNamedPolygon('C901_1') Or  IsNamedPolygon('SGND') Or  IsNamedPolygon('GND2') Or  IsNamedPolygon('GND1')] p21: connectstyle=Direct reliefconductorwidth=10 reliefentries=4 polygonreliefangle="90 Angle" airgapwidth=10
PolygonConnect PolygonConnect_5 [All vs IsNamedPolygon('GND1') Or  IsNamedPolygon('GND1')] p22: connectstyle=Direct reliefconductorwidth=10 reliefentries=4 polygonreliefangle="90 Angle" airgapwidth=10
PolygonConnect PolygonConnect_4 [All vs IsNamedPolygon('C21_1') Or  IsNamedPolygon('C5_1') Or  IsNamedPolygon('C12_2') Or  IsNamedPolygon('C2_2') Or  IsNamedPolygon('C13_1') Or  IsNamedPolygon('C28_1') Or  IsNamedPolygon('C6_1') Or  IsNamedPolygon('GND') Or  IsNamedPolygon('GND2') Or  IsNamedPolygon('C14_1') Or  IsNamedPolygon('C13_1') Or  IsNamedPolygon('Q1_3') Or  IsNamedPolygon('C14_1') Or  IsNamedPolygon('C5_1') Or  IsNamedPolygon('GND2') Or  IsNamedPolygon('C28_1') Or  IsNamedPolygon('D5_2') Or  IsNamedPolygon('D6_2') Or  IsNamedPolygon('D2_1') Or  IsNamedPolygon('C12_2') Or  IsNamedPolygon('D2_1') Or  IsNamedPolygon('C4_1') Or  IsNamedPolygon('C4_1') Or  IsNamedPolygon('C2_2') Or  IsNamedPolygon('GND') Or  IsNamedPolygon('C33_1') Or  IsNamedPolygon('C9_1')] p23: connectstyle=Direct reliefconductorwidth=10 reliefentries=4 polygonreliefangle="90 Angle" airgapwidth=10
PolygonConnect PolygonConnect_3 [All vs IsNamedPolygon('C28_1') Or  IsNamedPolygon('C12_2') Or  IsNamedPolygon('C28_1') Or  IsNamedPolygon('C9_1') Or  IsNamedPolygon('D5_2') Or  IsNamedPolygon('C12_2') Or  IsNamedPolygon('C2_2') Or  IsNamedPolygon('C14_1') Or  IsNamedPolygon('C4_1') Or  IsNamedPolygon('C14_1') Or  IsNamedPolygon('D6_2') Or  IsNamedPolygon('GND2') Or  IsNamedPolygon('Q1_3') Or  IsNamedPolygon('C5_1') Or  IsNamedPolygon('D2_1') Or  IsNamedPolygon('C4_1') Or  IsNamedPolygon('C13_1') Or  IsNamedPolygon('C5_1') Or  IsNamedPolygon('C13_1') Or  IsNamedPolygon('C33_1') Or  IsNamedPolygon('D2_1') Or  IsNamedPolygon('GND') Or  IsNamedPolygon('GND') Or  IsNamedPolygon('GND2') Or  IsNamedPolygon('C2_2') Or  IsNamedPolygon('C6_1') Or  IsNamedPolygon('C21_1')] p24: connectstyle=Direct reliefconductorwidth=10 reliefentries=4 polygonreliefangle="90 Angle" airgapwidth=10
PolygonConnect PolygonConnect_2 [All vs IsNamedPolygon('C21_1') Or  IsNamedPolygon('C4_1') Or  IsNamedPolygon('D5_2') Or  IsNamedPolygon('C5_1') Or  IsNamedPolygon('C14_1') Or  IsNamedPolygon('C13_1') Or  IsNamedPolygon('C4_1') Or  IsNamedPolygon('C33_1') Or  IsNamedPolygon('C12_2') Or  IsNamedPolygon('D2_1') Or  IsNamedPolygon('C2_2') Or  IsNamedPolygon('C28_1') Or  IsNamedPolygon('C12_2') Or  IsNamedPolygon('D2_1') Or  IsNamedPolygon('C5_1') Or  IsNamedPolygon('Q1_3') Or  IsNamedPolygon('GND') Or  IsNamedPolygon('D6_2') Or  IsNamedPolygon('C6_1') Or  IsNamedPolygon('C2_2') Or  IsNamedPolygon('C14_1') Or  IsNamedPolygon('C28_1') Or  IsNamedPolygon('C13_1') Or  IsNamedPolygon('C9_1') Or  IsNamedPolygon('GND')] p25: connectstyle=Direct reliefconductorwidth=10 reliefentries=4 polygonreliefangle="90 Angle" airgapwidth=10
PolygonConnect PolygonConnect_1 [All vs IsNamedPolygon('C28_1') Or  IsNamedPolygon('D5_2') Or  IsNamedPolygon('C5_1') Or  IsNamedPolygon('C5_1') Or  IsNamedPolygon('D2_1') Or  IsNamedPolygon('C21_1') Or  IsNamedPolygon('C9_1') Or  IsNamedPolygon('C4_1') Or  IsNamedPolygon('C14_1') Or  IsNamedPolygon('C28_1') Or  IsNamedPolygon('C6_1') Or  IsNamedPolygon('C12_2') Or  IsNamedPolygon('C33_1') Or  IsNamedPolygon('C4_1') Or  IsNamedPolygon('C13_1') Or  IsNamedPolygon('C12_2') Or  IsNamedPolygon('D6_2') Or  IsNamedPolygon('C2_2') Or  IsNamedPolygon('C14_1') Or  IsNamedPolygon('D2_1') Or  IsNamedPolygon('C2_2') Or  IsNamedPolygon('C13_1')] p26: connectstyle=Direct reliefconductorwidth=10 reliefentries=4 polygonreliefangle="90 Angle" airgapwidth=10
PolygonConnect [All] p27: connectstyle=Relief reliefconductorwidth=10 reliefentries=4 polygonreliefangle="90 Angle" airgapwidth=10
RoutingVias ThermalPadVias [IsVia and InAnyComponent] p1: holewidth=7.87 width=19.68 viastyle="Through Hole" minholewidth=7.87 minwidth=19.68 maxholewidth=12.99 maxwidth=23.62
RoutingVias [All] p2: holewidth=16 width=34 viastyle="Through Hole" minholewidth=7.87 minwidth=20 maxholewidth=40 maxwidth=65
SilkToBoardRegionClearance [Not ((IsComment or IsDesignator) And (Hide <> 'False')) and not InRegion(1000,500,4000,800)] p1:
SilkToSilkClearance SilkToSilkClearance_Pb-FreeLogo [(HasFootprint('Pb-Free_Overlay_Medium') OR HasFootprint('Pb-Free_Overlay_Small')) vs (HasFootprint('Pb-Free_Overlay_Medium') OR HasFootprint('Pb-Free_Overlay_Small'))] p1: silktosilkclearance=0
SilkToSilkClearance [All] p2: silktosilkclearance=1
SilkToSolderMaskClearance "Silk to Solder Mask Opening" [All] p1: minsilkscreentomaskgap=1 clearancetoexposedcopper=FALSE
SolderMaskExpansion [All] p1: expansion=1.97
Width [All] p1: maxlimit=100 minlimit=6 preferedwidth=10 checkconnectedcopper=TRUE
14 further rules are at their usual default settings.

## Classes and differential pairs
net class MV: NetR602_1 NetU105_8 NetU105_9 NetU105_10 NetU105_14
component class TIDM-1007_Control: C600 C601 C602 C603 C604 C605 C606 C607 C608 C609 C610 C611 C612 C613 C614 C615 C616 C617 J600 J601 J602 J603 R600 R601 R602 R603 R604 R605 R606 R607 R608 R609 R610 R611 R612 R613 R614 R615 R616 R617 R618 R619 R620 R621 R622 R623 R624 R625 R626 R627 R628 R629 R630 R631 R632 R633 R? TP600 TP601 TP602 TP603 TP604 TP605 TP606 TP607 TP608 TP609 U600 U601 U602
component class TIDM-1007_Power: !PCB100 C100 C101 C102 C103 C104 C105 C106 C107 C108 C109 C110 C111 C112 C113 C114 C115 C116 C117 C118 C119 C120 C121 C122 C123 C124 C125 C126 C127 C128 C129 C130 C131 C132 C133 C134 C135 C136 C137 C138 C139 C140 D100 D101 D102 D103 D104 D105 D106 D107 F100 H? J101 J102 J103 J104 K100 L100 L101 L102 L103 L104 Q100 Q101 Q102 R100 R101 R102 R103 R104 R105 R106 R107 R108 R109 R110 R111 R112 R113 R114 R115 R116 R117 R118 R119 R120 R121 R122 R123 R124 R125 R126 R127 R128 R129 R130 R131 R132 R133 R134 RT100 RT101 RV100 TP100 TP101 TP102 TP103 TP104 TP105 TP106 TP107 TP108 TP109 TP110 TP111 TP112 U100 U101 U102 U103 U104 U105
net class HV: -BRDG_N AC_L AC_N HVBUS NetC107_1 NetC109_1 NetC109_2 NetC110_2 NetC113_1 NetC135_1 NetD101_1 NetD101_2 NetF100_2 NetL100_1 NetL101_1 NetL102_1 SWNODE1 SWNODE2 SWNODE3

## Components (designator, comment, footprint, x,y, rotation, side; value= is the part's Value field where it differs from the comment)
C100 "EKMW451VSN221MP40S" KMW_2200x4000 9160,870 r270 top value=220uF
C101 "EKMW451VSN221MP40S" KMW_2200x4000 8180,870 r0 top value=220uF
C102 "EKMW451VSN221MP40S" KMW_2200x4000 5770,880 r0 top value=220uF
C103 "EKMW451VSN221MP40S" KMW_2200x4000 3030,1040 r0 top value=220uF
C104 "GRM32DR72J473KW01L" 1210_220 9410,480 r180 bottom value=0.047uF
C105 "GRM32DR72J473KW01L" 1210_220 9410,350 r180 bottom value=0.047uF
C106 "B58031I5105M002" B58031I_1084x785x450 1470,380 r0 bottom value=1uF
C107 "DE1B3RA101KN4AN01F" DE1_600x400x900 2290,2290 r90 top value=220pF
C108 "DE1B3RA101KN4AN01F" DE1_600x400x900 4020,2240 r90 top value=220pF
C109 "B32923C3334M" B32923_15mm 1010,2660 r90 top value=0.33uF
C110 "B32923C3334M" B32923_15mm 2740,2660 r90 top value=0.33uF
C111 "GRM155R70J104KA01D" 0402 6580,1400 r0 bottom value=0.1uF
C112 "DE1B3RA101KN4AN01F" DE1_600x400x900 2290,2910 r90 top value=220pF
C113 "DE1B3RA101KN4AN01F" DE1_600x400x900 4020,2940 r270 top value=220pF
C114 "890324026034" WCAP-FTX2_2600x1500x2500 4470,2650 r90 top value=2.2uF
C115 "GRM185R60J105KE26D" 0603 6590,1460 r0 bottom value=1uF
C116 "06035A102KAT2A" 0603 6690,1330 r90 bottom value=1000pF
C117 "B58031I5105M002" B58031I_1084x785x450 4180,380 r0 bottom value=1uF
C118 "GRM155R70J104KA01D" 0402 6410,2000 r0 bottom value=0.1uF
C119 "GRM185R60J105KE26D" 0603 6420,1948.98 r0 bottom value=1uF
C120 "GRM188R71C102KA01D" 0603 6388.35,2998.54 r0 bottom value=1000pF
C121 "GRM155R70J104KA01D" 0402 4610,1040 r270 bottom value=0.1uF
C122 "0805YD105KAT2A" 0805_HV 6570,2580 r90 top value=1uF
C123 "GRM185R60J105KE26D" 0603 4670,1030 r270 bottom value=1uF
C124 "GRM155R70J104KA01D" 0402 6360,1870 r0 bottom value=0.1uF
C125 "06035A102KAT2A" 0603 4540,950 r0 bottom value=1000pF
C126 "B58031I5105M002" B58031I_1084x785x450 6600,380 r0 bottom value=1uF
C127 "GRM155R60J102KA01D" 0402 6360,2100 r0 bottom value=1000pF
C128 "GRM155R60J102KA01D" 0402 6360,2150 r0 bottom value=1000pF
C129 "GRM155R70J223KA01D" 0402 6360,2050 r180 bottom value=0.022uF
C130 "GRM155R70J104KA01D" 0402 1880,1050.32 r270 bottom value=0.1uF
C131 "GRM155R70J104KA01D" 0402 6280,1990 r90 top value=0.1uF
C132 "GRM185R60J105KE26D" 0603 1940,1040.32 r270 bottom value=1uF
C133 "GRM155R70J104KA01D" 0402 6417.5,1920 r180 top value=0.1uF
C134 "06035A102KAT2A" 0603 1810,950.32 r0 bottom value=1000pF
C135 "0805YD106MAT2A" 0805_HV 4860,2130 r270 bottom value=10uF
C136 "C0603X103K5RACTU" 0603 5270,1980 r90 bottom value=0.01uF
C137 "0805YD106MAT2A" 0805_HV 4770,2130 r270 bottom value=10uF
C138 "C1608X7R1E105K080AB" 0603 4980,2120 r90 top value=1uF
C139 "06035A102KAT2A" 0603 5298.54,2230 r0 bottom value=1000pF
C140 "06035A102KAT2A" 0603 5268.35,2140 r270 bottom value=1000pF
C600 "C1608X7R1E105K080AB" 0603 7310,2830 r180 bottom value=1uF
C601 "GRM155R70J103KA01D" 0402 7151.81,2960 r270 bottom value=0.01uF
C602 "GCM155R71C104KA55D" 0402 7340,2750 r270 bottom value=0.1uF
C603 "GRM155R60J104KA01D" 0402 7090,3230 r270 bottom value=0.1uF
C604 "GRM155R70J103KA01D" 0402 7270,2962.2 r270 bottom value=0.01uF
C605 "C1608X7R1E105K080AB" 0603 6900,2660 r180 bottom value=1uF
C606 "CGA2B2X7R1H471K050BA" 0402 7288.5,3190 r90 bottom value=470pF
C607 "GRM155R70J103KA01D" 0402 7430,2900 r270 bottom value=0.01uF
C608 "C1005X5R1A473K050BA" 0402 7140,3090 r270 bottom value=0.047uF
C609 "CGA2B2X7R1H471K050BA" 0402 7190,3090 r270 bottom value=470pF
C610 "CGA2B2X7R1H471K050BA" 0402 7190,3230 r90 bottom value=470pF
C611 "GRM155R70J103KA01D" 0402 7901.81,3070 r270 bottom value=0.01uF
C612 "GRM155R70J103KA01D" 0402 8000,3070 r270 bottom value=0.01uF
C613 "GRM155R70J103KA01D" 0402 8100,3080 r270 bottom value=0.01uF
C614 "GRM1555C1E470JA01D" 0402 6780,2941.81 r180 bottom value=47pF
C615 "C1608X7R1E105K080AB" 0603 7740,270 r270 bottom value=1uF
C616 "C1608X7R1E105K080AB" 0603 8280,270 r270 bottom value=1uF
C617 "GRM155R70J103KA01D" 0402 7840,2960 r270 bottom value=0.01uF
D100 "US1K-13-F" SMA 7330,2190 r270 bottom value=800V
D101 "STPS130A" SMA 4850,1820 r270 bottom value=30V
D102 "D25XB60-7000" 5S 5590,1430 r0 top value=600V
D103 "STPS130A" SMA 5690,1990 r270 top value=30V
D104 "US1K-13-F" SMA 6490,2440 r90 bottom value=800V
D105 "MMSZ4699T1G" SOD-123 6350,2900 r0 top value=12V
D106 "BAS316,115" sod-323 6500,2900 r180 top value=100V
D107 "MURA160T3G" SMA 5110,2240 r0 top value=600V
F100 "0325020.MXP" FUSE_0325_Verical 290,2350 r135 top
J101 "0448120024" Molex_0448120024 5803.45,262 r0 bottom
J102 "0448120024" Molex_0448120024 3195,262 r0 bottom
J103 "0448120024" Molex_0448120024 625,262 r0 bottom
J104 "282856-3" TE_282856-3 9330,200 r0 top
J600 "HSEC8-160-01-L-DV-A-BL" controlCARD-120HSEC 7960,3140 r0 top
J601 "DF59-3S-2V(51)" Hirose_DF59-3S-2V_51 7850,0 r0 top
J602 "DF59-3S-2V(51)" Hirose_DF59-3S-2V_51 8350,-1.41 r0 top
J603 "DF59-3S-2V(51)" Hirose_DF59-3S-2V_51 8750,-1.41 r0 top
K100 "875B-1CC-F-S-12VDC" RELAY_875 6090,2520 r90 top
L100 "G164005LF" IND_7840-09-0014 6700,1100 r0 top
L101 "G164005LF" IND_7840-09-0014 4190,960 r270 top
L102 "G164005LF" IND_7840-09-0014 1470,960 r270 top
L103 "7448051507" WE-CMBNC_XL 1730,2600 r0 top value=7mH
L104 "7448051012" WE-CMBNC_XL 3460,2600 r0 top value=12mH
Q100 "STY145N65M5" TO-247 5240,1750 r0 top value=650V
Q101 "STY145N65M5" TO-247 5890,1750 r0 top value=650V
Q102 "2N7002ET1G" SOT-23 6390,2888.54 r270 bottom value=60V
R100 "RT0805BRD07348KL" 0805_HV 7270,2520 r270 bottom value=348k
R101 "RT0805BRD07348KL" 0805_HV 7360,2430 r270 bottom value=348k
R102 "RT0805BRD07348KL" 0805_HV 7450,2340 r270 bottom value=348k
R103 "CRCW080510R0FKEA" 0805_HV 4990,1920 r90 top value=10.0
R104 "ERJ-6ENF4991V" 0805_HV 5080,1920 r90 top value=4.99k
R105 "CRCW1206330KJNEA" 1206 1560,2380 r270 bottom value=330k
R106 "CRCW1206330KJNEA" 1206 1320,2380 r270 bottom value=330k
R107 "CRCW1206330KJNEA" 1206 1440,2380 r270 bottom value=330k
R108 "CRCW1206330KJNEA" 1206 1560,2620 r270 bottom value=330k
R109 "CRCW1206330KJNEA" 1206 1320,2620 r270 bottom value=330k
R110 "CRCW1206330KJNEA" 1206 1440,2620 r270 bottom value=330k
R111 "CRCW1206330KJNEA" 1206 1560,2860 r270 bottom value=330k
R112 "CRCW1206330KJNEA" 1206 1320,2860 r270 bottom value=330k
R113 "CRCW1206330KJNEA" 1206 1440,2860 r270 bottom value=330k
R114 "CRCW080510R0FKEA" 0805_HV 5530,1980 r180 top value=10.0
R115 "ERJ-6ENF4991V" 0805_HV 5530,1890 r180 top value=4.99k
R116 "CRCW040210K0FKED" 0402 6312,1850 r0 top value=10.0k
R117 "CRCW040212K7FKED" 0402 6230,1940 r90 top value=12.7k
R118 "CRCW1206150RJNEA" 1206 6569.69,2760 r270 top value=150
R119 "RT0805BRD07348KL" 0805_HV 7000,2270 r270 bottom value=348k
R120 "CRCW1206150RJNEA" 1206 6534.25,2760 r270 bottom value=150
R121 "RT0805BRD07348KL" 0805_HV 7000,2430 r270 bottom value=348k
R122 "RC0603FR-0710KL" 0603 6390,3068.54 r180 bottom value=10.0k
R123 "RT0805BRD07348KL" 0805_HV 7090,2520 r270 bottom value=348k
R124 "CRCW04025K49FKED" 0402 6360,1820 r180 bottom value=5.49k
R125 "CRCW0402330KJNED" 0402 6334.03,1973.07 r90 bottom value=330k
R126 "CRCW0603200RFKEA" 0603 5270,2230 r90 top value=200
R127 "CRCW04021K00JNED" 0402 5320,2290 r0 bottom value=1.0k
R128 "CRCW04021K00JNED" 0402 5296.89,2130 r0 top value=1.0k
R129 "CRCW1206330KJNEA" 1206 9550,1070 r90 bottom value=330k
R130 "CRCW1206330KJNEA" 1206 9550,870 r90 bottom value=330k
R131 "CRCW1206330KJNEA" 1206 9550,670 r90 bottom value=330k
R132 "CRCW06030000Z0EA" 0603 5970,80 r0 bottom value=0
R133 "CRCW06030000Z0EA" 0603 3400,80 r0 bottom value=0
R134 "CRCW06030000Z0EA" 0603 810,80 r0 bottom value=0
R600 "CRCW04021K40FKED" 0402 7101.81,2960 r90 bottom value=1.40k
R601 "CRCW04023K57FKED" 0402 7180,2850 r0 bottom value=3.57k
R602 "RT0805BRD07348KL" 0805_HV 7500,2820 r270 bottom value=348k
R603 "CRCW04021K40FKED" 0402 7220,2960.07 r90 bottom value=1.40k
R604 "CRCW040210K0JNED" 0402 7040,3230 r90 bottom value=10k
R605 "RT0805BRD07348KL" 0805_HV 7500,2980 r270 bottom value=348k
R606 "CRCW04023K57FKED" 0402 7100,2830 r270 bottom value=3.57k
R607 "RT0805BRD07348KL" 0805_HV 7450,3140 r270 bottom value=348k
R608 "CRCW04021K40FKED" 0402 7380,2960 r90 bottom value=1.40k
R609 "CRCW08057K50FKEA" 0805_HV 7360,3180 r270 bottom value=7.50k
R610 "CRCW04021K00FKED" 0402 7180,2800 r180 bottom value=1.00k
R611 "CRCW040233R2FKED" 0402 7040,3090 r270 bottom value=33.2
R612 "CRCW040210K0FKED" 0402 7130,2748.19 r0 bottom value=10.0k
R613 "ERA-2AEB4871X" 0402 7090,3090 r90 bottom value=4.87k
R614 "CRCW04020000Z0ED" 0402 7130,2698.19 r0 bottom value=0
R615 "CRCW040210K0FKED" 0402 7020,2660 r0 bottom value=10.0k
R616 "CRCW04027K50FKED" 0402 7240,3090 r90 bottom value=7.50k
R617 "CRCW04027K50FKED" 0402 7140,3230 r270 bottom value=7.50k
R618 "CRCW04024K99FKED" 0402 7847.97,3110 r270 bottom value=4.99k
R619 "CRCW04021K00FKED" 0402 6890,2941.81 r0 bottom value=1.00k
R620 "CRCW04024K99FKED" 0402 7797.97,3110 r270 bottom value=4.99k
R621 "CRCW04020000Z0ED" 0402 7900,3200 r90 bottom value=0
R622 "CRCW040210K0FKED" 0402 6740,2810 r270 bottom value=10.0k
R623 "CRCW040210K0FKED" 0402 6690,2810 r90 bottom value=10.0k
R624 "CRCW04024K99FKED" 0402 7747.97,3110 r270 bottom value=4.99k
R625 "CRCW04020000Z0ED" 0402 7950,3200 r90 bottom value=0
R626 "CRCW04020000Z0ED" 0402 8000,3200 r90 bottom value=0
R627 "CRCW040210K0FKED" 0402 6810,2640 r270 bottom value=10.0k
R628 "CRCW040210K0FKED" 0402 6760,2640 r270 bottom value=10.0k
R629 "CRCW040210K0FKED" 0402 6710,2640 r270 bottom value=10.0k
R630 "CRCW04021K40FKED" 0402 7790,2960 r90 bottom value=1.40k
R631 "CRCW04029K31FKED" 0402 7950,3070 r90 bottom value=9.31k
R632 "CRCW04029K31FKED" 0402 8050,3080 r90 bottom value=9.31k
R633 "CRCW04029K31FKED" 0402 8150,3080 r90 bottom value=9.31k
RT100 "B59751B0120A070" TDK_B751 5420,2590 r0 top value=50
RT101 "B59751B0120A070" TDK_B751 5130,2590 r0 top value="50 ohm"
RV100 "S10K275E2" VAR_S10K275E2 330,2750 r290 top
TP100 "Vo" Keystone5000 9550,1250 r0 top value=Red
TP101 "L" Keystone5000 100,2100 r0 top value=Red
TP102 "PGND_PFC" Keystone5001 9550,500 r0 top value=Black
TP103 "N" Keystone5001 100,3100 r0 top value=Black
TP104 "Suggest using a net name here" Mill-Max_0312-0-15-15-34-27-10-0 6953.45,100 r0 top
TP105 "Suggest using a net name here" Mill-Max_0312-0-15-15-34-27-10-0 7353.45,100 r0 top
TP106 "Suggest using a net name here" Mill-Max_0312-0-15-15-34-27-10-0 6753.45,100 r0 top
TP107 "Suggest using a net name here" Mill-Max_0312-0-15-15-34-27-10-0 4345,100 r0 top
TP108 "Suggest using a net name here" Mill-Max_0312-0-15-15-34-27-10-0 4745,100 r0 top
TP109 "Suggest using a net name here" Mill-Max_0312-0-15-15-34-27-10-0 4145,100 r0 top
TP110 "Suggest using a net name here" Mill-Max_0312-0-15-15-34-27-10-0 1775,100 r0 top
TP111 "Suggest using a net name here" Mill-Max_0312-0-15-15-34-27-10-0 2175,100 r0 top
TP112 "Suggest using a net name here" Mill-Max_0312-0-15-15-34-27-10-0 1575,100 r0 top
